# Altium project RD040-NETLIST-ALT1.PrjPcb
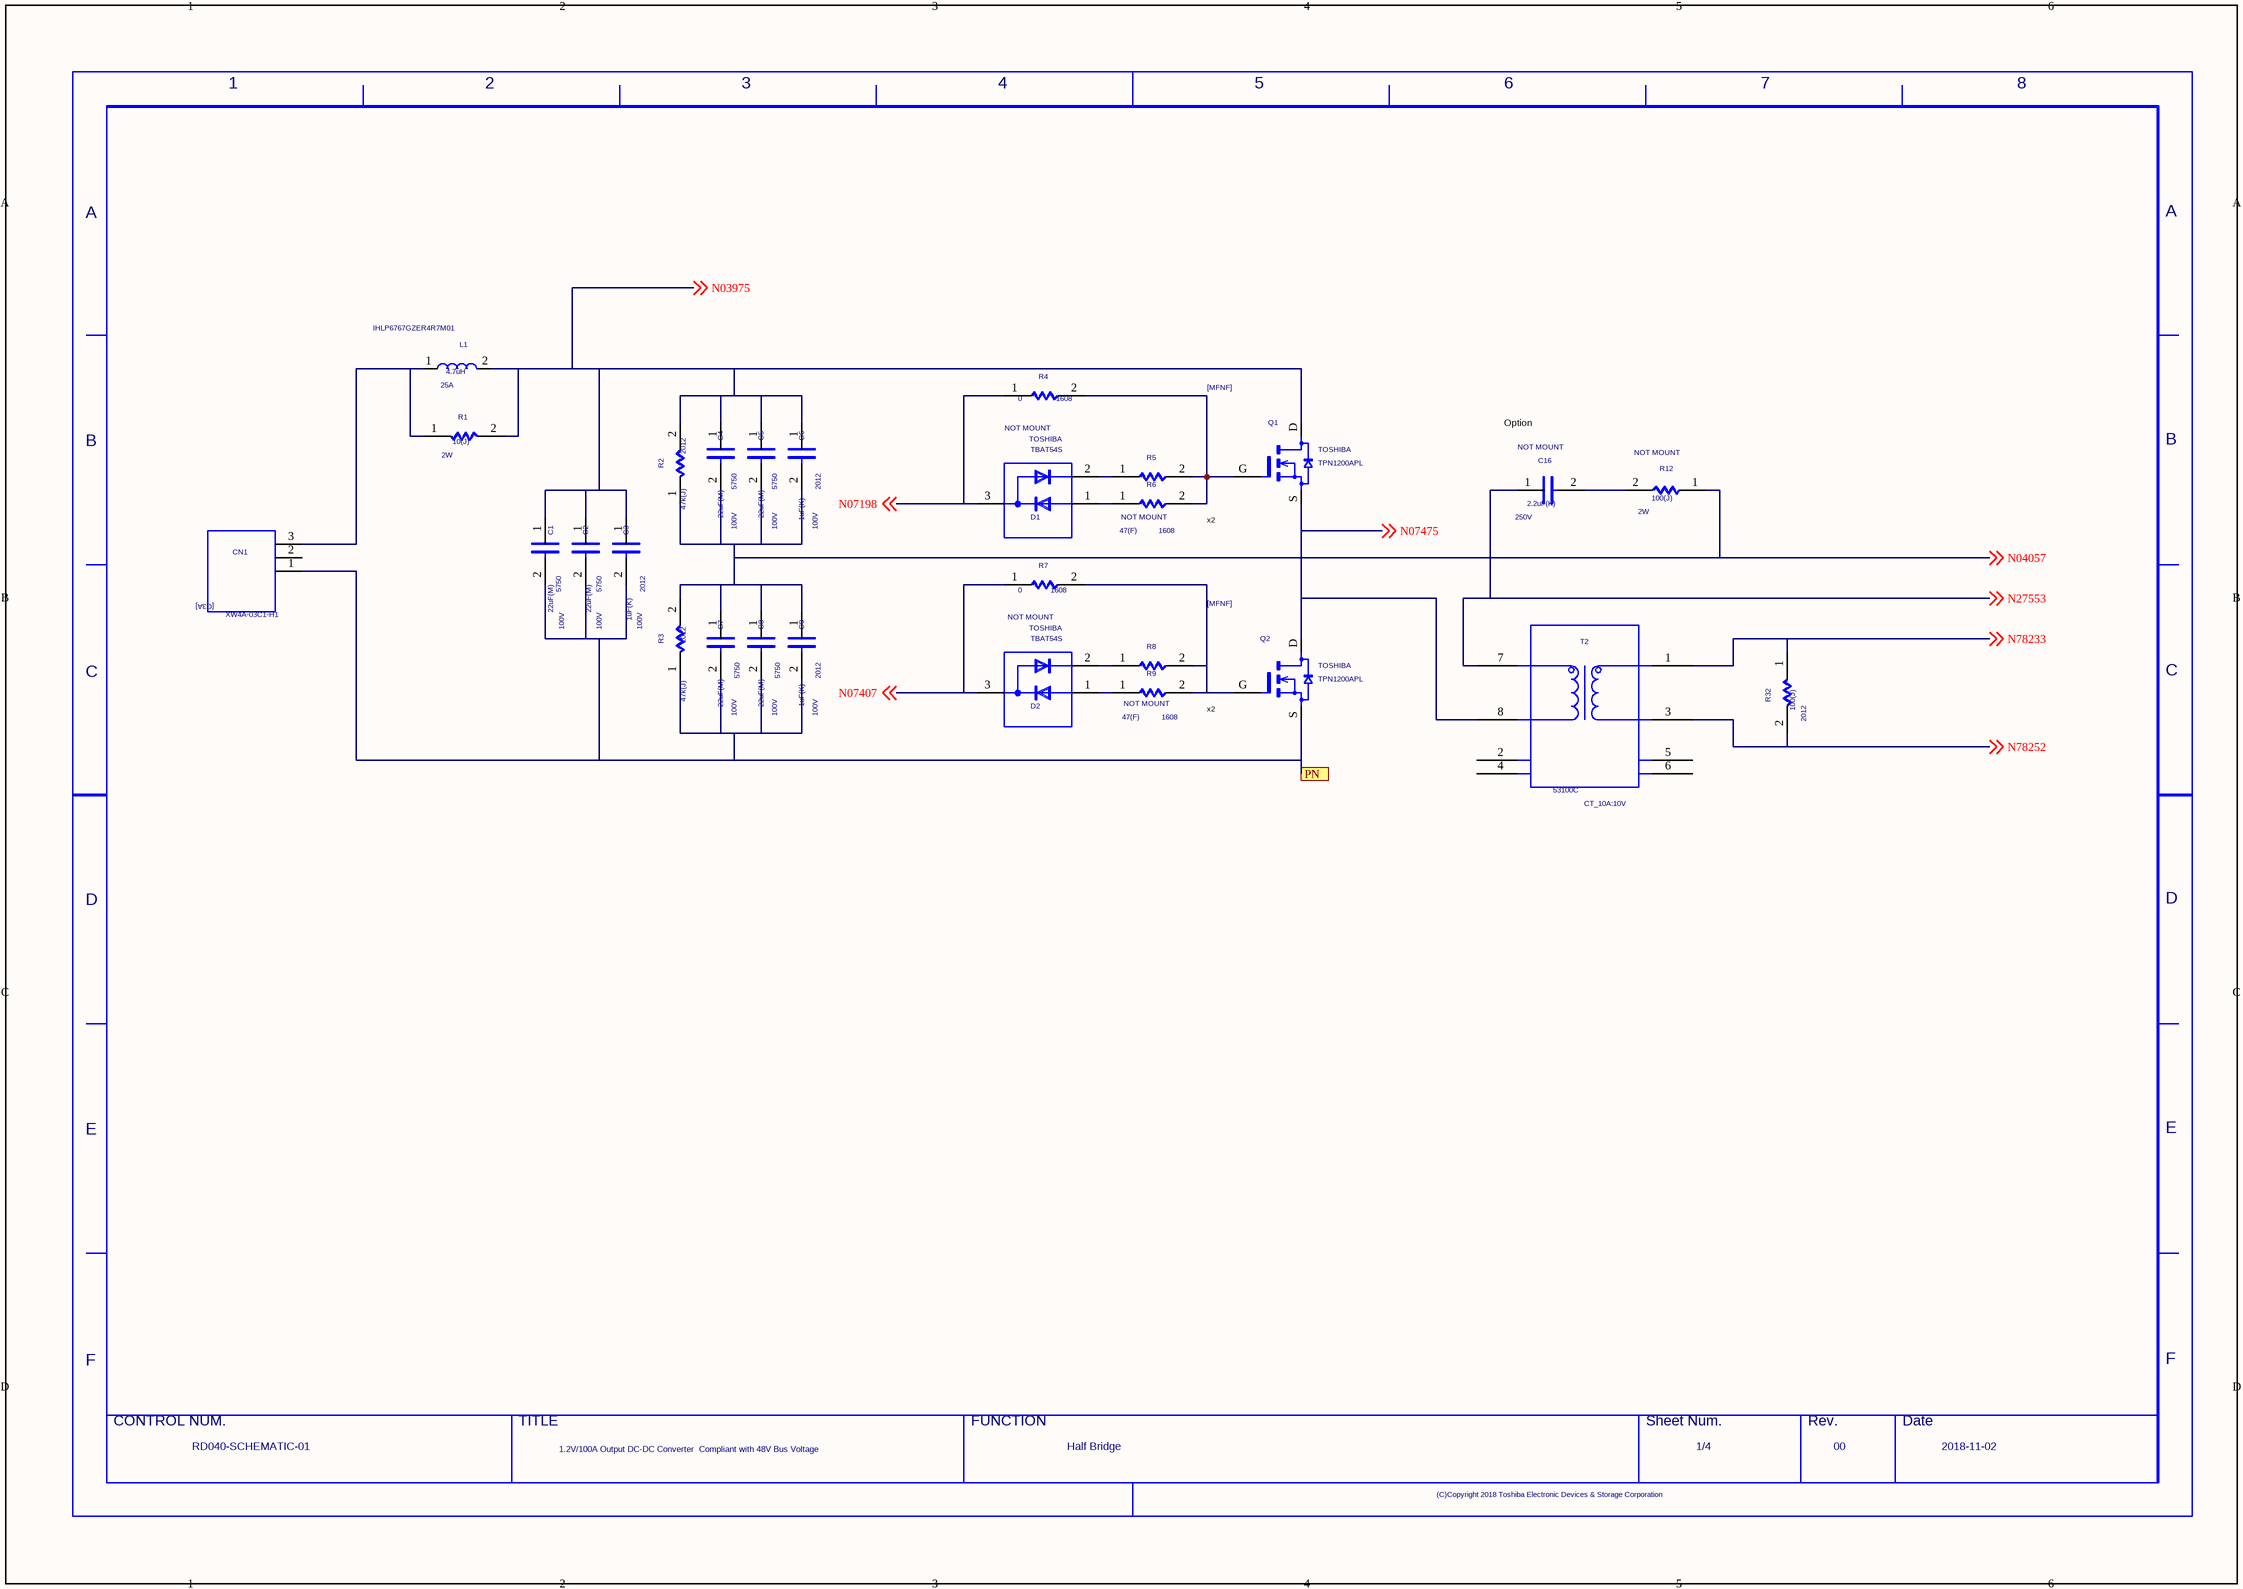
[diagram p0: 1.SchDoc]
4 sheets, 137 parts. Net scope: flat (ports and power ports of the same name join across sheets).
Sheets:
  1.SchDoc
  2.SchDoc
  3.SchDoc
  4.SchDoc

## Sheet 1.SchDoc
size 420 x 297 mm

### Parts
(Parts that share a designator on the sheet are numbered #1, #2 ... from top to bottom, then left to right.)
C1  COMPCOMMENT: 5750  VAL2: 100V  VAL1: 22uF(M)  [CHIP-5750]  (hidden comment: 22uF-M_100V)
C2  COMPCOMMENT: 5750  VAL2: 100V  VAL1: 22uF(M)  [CHIP-5750]  (hidden comment: 22uF-M_100V)
C3  VAL2: 100V  VAL1: 1uF(K)  COMPCOMMENT: 2012  [CHIP-2012]  (hidden comment: 1uF-K_100V)
C4  COMPCOMMENT: 5750  VAL2: 100V  VAL1: 22uF(M)  [CHIP-5750]  (hidden comment: 22uF-M_100V)
C5  COMPCOMMENT: 5750  VAL2: 100V  VAL1: 22uF(M)  [CHIP-5750]  (hidden comment: 22uF-M_100V)
C6  VAL2: 100V  VAL1: 1uF(K)  COMPCOMMENT: 2012  [CHIP-2012]  (hidden comment: 1uF-K_100V)
C7  COMPCOMMENT: 5750  VAL2: 100V  VAL1: 22uF(M)  [CHIP-5750]  (hidden comment: 22uF-M_100V)
C8  COMPCOMMENT: 5750  VAL2: 100V  VAL1: 22uF(M)  [CHIP-5750]  (hidden comment: 22uF-M_100V)
C9  COMPCOMMENT: 2012  VAL2: 100V  VAL1: 1uF(K)  [CHIP-2012]  (hidden comment: 1uF-K_100V)
C16  VAL1: 2.2uF(K)  VAL2: 250V  NOTMOUNT: NOT MOUNT  (hidden comment: C)
CN1  XW4A-03C1-H1  [SIP-3]
D1  NOTMOUNT: NOT MOUNT  USERCOMPTEXT3: TOSHIBA  [SOT23-3]  (hidden comment: TBAT54S)
D2  NOTMOUNT: NOT MOUNT  USERCOMPTEXT3: TOSHIBA  [SOT23-3]  (hidden comment: TBAT54S)
L1  VAL3: IHLP6767GZER4R7M01  VAL2: 25A  VAL1: 4.7uH  [SMD-6767]  (hidden comment: 4u7H-M_6767)
Q1  USERCOMPTEXT3: TOSHIBA  [TSON-8]  (hidden comment: TPN1200APL)
Q2  USERCOMPTEXT3: TOSHIBA  [TSON-8]  (hidden comment: TPN1200APL)
R1  VAL2: 2W  VAL1: 10(J)  [Axial-2]  (hidden comment: 10-J_2W)
R2  COMPCOMMENT: 2012  VAL1: 47k(J)  [CHIP-2012]  (hidden comment: 47k-J_2012)
R3  COMPCOMMENT: 2012  VAL1: 47k(J)  [CHIP-2012]  (hidden comment: 47k-J_2012)
R4  VAL1: 0  COMPCOMMENT: 1608  [CHIP-1608]  (hidden comment: NM_1608)
R5  NOTMOUNT: NOT MOUNT  VAL1: 47(F)  COMPCOMMENT: 1608  [CHIP-1608]  (hidden comment: 47-F_1608)
R6  47-F_1608  [CHIP-1608]  (value not drawn)
R7  VAL1: 0  COMPCOMMENT: 1608  [CHIP-1608]  (hidden comment: NM_1608)
R8  NOTMOUNT: NOT MOUNT  VAL1: 47(F)  COMPCOMMENT: 1608  [CHIP-1608]  (hidden comment: 47-F_1608)
R9  47-F_1608  [CHIP-1608]  (value not drawn)
R12  VAL2: 2W  VAL1: 100(J)  NOTMOUNT: NOT MOUNT  (hidden comment: R)
R32  COMPCOMMENT: 2012  VAL1: 100(J)  [CHIP-2012]  (hidden comment: 100-J_2012)
T2  CT_10A:10V
U?#1  DATE: 2018-11-02  FUNCTION: Half Bridge  TITLE: 1.2V/100A Output DC-DC Converter / Compliant with 48V Bus Voltage  DRAWINGNUMBER: RD040-SCHEMATIC-01  REVISION: 00  SHEETNUMBER: 1/4  (hidden comment: WAKU_DEF100_2018)

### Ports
PN

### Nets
N03975: C1.1 C2.1 C3.1 C4.1 C5.1 C6.1 L1.2 Q1.D R1.2 R2.2 ; off-sheet N03975
N04057: C4.2 C5.2 C6.2 C7.1 C8.1 C9.1 R2.1 R3.2 R12.1 ; off-sheet N04057
N07028: Q1.G R4.2 R5.2 R6.2
N07195: Q2.G R7.2 R8.2 R9.2
N07198: D1.3 R4.1 ; off-sheet N07198
N07407: D2.3 R7.1 ; off-sheet N07407
N07475: Q1.S Q2.D T2.8 ; off-sheet N07475
N08432: CN1.3 L1.1 R1.1
N27526: C16.2 R12.2
N27553: C16.1 T2.7 ; off-sheet N27553
N75033: D1.1 R6.1
N75062: D1.2 R5.1
N76065: D2.1 R9.1
N76205: D2.2 R8.1
N78233: R32.1 T2.1 ; off-sheet N78233
N78252: R32.2 T2.3 ; off-sheet N78252
SIG170: C1.2 C2.2 C3.2 C7.2 C8.2 C9.2 CN1.1 Q2.S R3.1 ; port PN

Not connected (* = marked no-connect by the designer): CN1 2; T2 2 4 5 6

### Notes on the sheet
- Option
- x2

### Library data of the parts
C1 = C: OriginalSymbolOrigin: (2540,7620); VAL3: KRM55WR72A226M; COMPONENTNAME: C_C; MAKER: Murata; INSTANCENAME: I04446; SAVECOUNT: 1; UPDATETIME: 16:59:57; UPDATEUSER: w20070dm; PIN NAMES VISIBLE: False; PIN NAMES ROTATE: True
C2 = C: OriginalSymbolOrigin: (2540,7620); VAL3: KRM55WR72A226M; COMPONENTNAME: C_C; MAKER: Murata; INSTANCENAME: I04482; SAVECOUNT: 1; UPDATETIME: 16:59:57; UPDATEUSER: w20070dm; PIN NAMES VISIBLE: False; PIN NAMES ROTATE: True
C3 = C: OriginalSymbolOrigin: (2540,7620); VAL3: GRM21BC72A105K; COMPONENTNAME: C_C; MAKER: Murata; INSTANCENAME: I04414; SAVECOUNT: 1; UPDATETIME: 16:59:57; UPDATEUSER: w20070dm; PIN NAMES VISIBLE: False; PIN NAMES ROTATE: True
C4 = C: OriginalSymbolOrigin: (2540,7620); VAL3: KRM55WR72A226M; COMPONENTNAME: C_C; MAKER: Murata; INSTANCENAME: I60867; SAVECOUNT: 1; UPDATETIME: 16:59:57; UPDATEUSER: w20070dm; PIN NAMES VISIBLE: False; PIN NAMES ROTATE: True
C5 = C: OriginalSymbolOrigin: (2540,7620); VAL3: KRM55WR72A226M; COMPONENTNAME: C_C; MAKER: Murata; INSTANCENAME: I60839; SAVECOUNT: 1; UPDATETIME: 16:59:57; UPDATEUSER: w20070dm; PIN NAMES VISIBLE: False; PIN NAMES ROTATE: True
C6 = C: OriginalSymbolOrigin: (2540,7620); VAL3: GRM21BC72A105K; COMPONENTNAME: C_C; MAKER: Murata; INSTANCENAME: I60803; SAVECOUNT: 1; UPDATETIME: 16:59:57; UPDATEUSER: w20070dm; PIN NAMES VISIBLE: False; PIN NAMES ROTATE: True
C7 = C: OriginalSymbolOrigin: (2540,7620); VAL3: KRM55WR72A226M; COMPONENTNAME: C_C; MAKER: Murata; INSTANCENAME: I61562; SAVECOUNT: 1; UPDATETIME: 16:59:57; UPDATEUSER: w20070dm; PIN NAMES VISIBLE: False; PIN NAMES ROTATE: True
C8 = C: OriginalSymbolOrigin: (2540,7620); VAL3: KRM55WR72A226M; COMPONENTNAME: C_C; MAKER: Murata; INSTANCENAME: I61642; SAVECOUNT: 1; UPDATETIME: 16:59:57; UPDATEUSER: w20070dm; PIN NAMES VISIBLE: False; PIN NAMES ROTATE: True
C9 = C: OriginalSymbolOrigin: (2540,7620); VAL3: GRM21BC72A105K; COMPONENTNAME: C_C; MAKER: Murata; INSTANCENAME: I61594; SAVECOUNT: 1; UPDATETIME: 16:59:57; UPDATEUSER: w20070dm; PIN NAMES VISIBLE: False; PIN NAMES ROTATE: True
C16 = C: OriginalSymbolOrigin: (2540,7620); VAL3: ECQE2225KB
CN1 = C3A: PARTNAME: PIN-HEADER_3x1; SAVEAREA0: -6798,-236,26764,20869; TIME: 09:53:04; UPDATEUSER: tomizawa-y; UPDATETIME: 09:53:12; SAVECOUNT: 2; OriginalSymbolOrigin: (2540,17780); FUNCTION: PIN-HEADER_3x1_PIN-HEADER_3x1.Normal_package; MAKER: Omron; INSTANCENAME: I08244; NUMBER DEVICES IN PACKAGE: 1; PIN NAMES VISIBLE: False; PIN NAMES ROTATE: True
D1 = DML: PARTNAME: 1SS226; SAVEAREA0: -6496,-188,29064,18281; TIME: 11:11:28; UPDATEUSER: cae; UPDATETIME: 11:19:31; SAVECOUNT: 3; OriginalSymbolOrigin: (5080,17780); FUNCTION: 1SS226_1SS226.Normal_package; INSTANCENAME: I71543; NUMBER DEVICES IN PACKAGE: 1; PIN NAMES VISIBLE: False; PIN NAMES ROTATE: True
D2 = DML: PARTNAME: 1SS226; SAVEAREA0: -6496,-188,29064,18281; TIME: 11:11:28; UPDATEUSER: cae; UPDATETIME: 11:19:31; SAVECOUNT: 3; OriginalSymbolOrigin: (5080,17780); FUNCTION: 1SS226_1SS226.Normal_package; INSTANCENAME: I78427; NUMBER DEVICES IN PACKAGE: 1; PIN NAMES VISIBLE: False; PIN NAMES ROTATE: True
L1 = L: PARTNAME: INDUCTOR; OriginalSymbolOrigin: (2540,5080); COMPONENTNAME: INDUCTOR_INDUCTOR; MAKER: Vishay; INSTANCENAME: I20636496; SAVECOUNT: 1; UPDATETIME: 16:59:57; UPDATEUSER: w20070dm; PIN NAMES VISIBLE: False; ORDER: 0; PIN NAMES ROTATE: True
Q1 = MFNF: PARTNAME: MOSFET_N(D); SAVECOUNT: 11; SAVEAREA0: -7027,-292,21786,15988; OriginalSymbolOrigin: (5080,12700); FUNCTION: MOSFET_N(D)_MOSFET_N(D).Normal_package; INSTANCENAME: I69029; UPDATETIME: 16:59:57; UPDATEUSER: w20070dm; NUMBER DEVICES IN PACKAGE: 1; PIN NAMES VISIBLE: False; PIN NAMES ROTATE: True
Q2 = MFNF: PARTNAME: MOSFET_N(D); SAVECOUNT: 11; SAVEAREA0: -7027,-292,21786,15988; OriginalSymbolOrigin: (5080,12700); FUNCTION: MOSFET_N(D)_MOSFET_N(D).Normal_package; INSTANCENAME: I69405; UPDATETIME: 16:59:57; UPDATEUSER: w20070dm; NUMBER DEVICES IN PACKAGE: 1; PIN NAMES VISIBLE: False; PIN NAMES ROTATE: True
R1 = R: OriginalSymbolOrigin: (5080,5080); VAL3: MOS2CT52A100J; COMPONENTNAME: R_R; MAKER: ROHM; INSTANCENAME: I62527; SAVECOUNT: 1; UPDATETIME: 16:59:57; UPDATEUSER: w20070dm; PIN NAMES VISIBLE: False; PIN NAMES ROTATE: True
R2 = R: OriginalSymbolOrigin: (5080,5080); VAL2: 0.4W; VAL3: ESR10EZPJ473; COMPONENTNAME: R_R; MAKER: ROHM; INSTANCENAME: I20654113; SAVECOUNT: 1; UPDATETIME: 16:59:57; UPDATEUSER: w20070dm; PIN NAMES VISIBLE: False; PIN NAMES ROTATE: True
R3 = R: OriginalSymbolOrigin: (5080,5080); VAL2: 0.4W; VAL3: ESR10EZPJ473; COMPONENTNAME: R_R; MAKER: ROHM; INSTANCENAME: I61482; SAVECOUNT: 1; UPDATETIME: 16:59:57; UPDATEUSER: w20070dm; PIN NAMES VISIBLE: False; PIN NAMES ROTATE: True
R4 = R: OriginalSymbolOrigin: (5080,5080); VAL3: MCR03EZHJ000; VAL2: 1/8W; COMPONENTNAME: R_R; MAKER: KOA; INSTANCENAME: I75159; SAVECOUNT: 1; UPDATETIME: 16:59:57; UPDATEUSER: w20070dm; PIN NAMES VISIBLE: False; PIN NAMES ROTATE: True
R5 = R: OriginalSymbolOrigin: (5080,5080); VAL3: RK73H1JTTD47R0F; COMPONENTNAME: R_R; MAKER: KOA; INSTANCENAME: I74967; SAVECOUNT: 1; UPDATETIME: 16:59:57; UPDATEUSER: w20070dm; PIN NAMES VISIBLE: False; PIN NAMES ROTATE: True
R6 = R: OriginalSymbolOrigin: (5080,5080); NOTMOUNT: NOT MOUNT; VAL1: 47(F); COMPCOMMENT: 1608; VAL3: RK73H1JTTD47R0F; COMPONENTNAME: R_R; MAKER: KOA; INSTANCENAME: I74991; SAVECOUNT: 1; UPDATETIME: 16:59:57; UPDATEUSER: w20070dm; PIN NAMES VISIBLE: False; PIN NAMES ROTATE: True
R7 = R: OriginalSymbolOrigin: (5080,5080); VAL2: 1/8W; VAL3: MCR03EZHJ000; COMPONENTNAME: R_R; MAKER: KOA; INSTANCENAME: I76137; SAVECOUNT: 1; UPDATETIME: 16:59:57; UPDATEUSER: w20070dm; PIN NAMES VISIBLE: False; PIN NAMES ROTATE: True
R8 = R: OriginalSymbolOrigin: (5080,5080); VAL3: RK73H1JTTD47R0F; COMPONENTNAME: R_R; MAKER: KOA; INSTANCENAME: I76161; SAVECOUNT: 1; UPDATETIME: 16:59:57; UPDATEUSER: w20070dm; PIN NAMES VISIBLE: False; PIN NAMES ROTATE: True
R9 = R: OriginalSymbolOrigin: (5080,5080); NOTMOUNT: NOT MOUNT; VAL1: 47(F); COMPCOMMENT: 1608; VAL3: RK73H1JTTD47R0F; COMPONENTNAME: R_R; MAKER: KOA; INSTANCENAME: I76085; SAVECOUNT: 1; UPDATETIME: 16:59:57; UPDATEUSER: w20070dm; PIN NAMES VISIBLE: False; PIN NAMES ROTATE: True
R12 = R: OriginalSymbolOrigin: (5080,5080); VAL3: MOS2CT52A101J
R32 = R: OriginalSymbolOrigin: (5080,5080); VAL3: ESR10EZPJ101; COMPONENTNAME: R_R; MAKER: ROHM; INSTANCENAME: I78881; SAVECOUNT: 1; UPDATETIME: 16:59:57; UPDATEUSER: w20070dm; PIN NAMES VISIBLE: False; PIN NAMES ROTATE: True
T2 = 53100C: PARTNAME: AF-TRANS(2B_murata); SAVEAREA0: -14581,-371,55282,35914; SAVECOUNT: 9; TIME: 14:27:07; UPDATEUSER: cae; UPDATETIME: 15:56:07; OriginalSymbolOrigin: (7620,33020); FUNCTION: AF-TRANS(2B_murata)_AF-TRANS(2B_murata).Normal_package; MAKER: Murata; INSTANCENAME: I67135; NUMBER DEVICES IN PACKAGE: 1; PIN NAMES VISIBLE: False; ORDER: 0; PIN NUMBERS VISIBLE: True
U?#1 = WAKU_DEF100_2018: PLOTTIME: HH:MM; SAVEAREA0: -45080,-4508,463680,304612; TIME: 14:09:12; UPDATEUSER: cae; UPDATETIME: 09:58:42; SAVECOUNT: 4; OriginalSymbolOrigin: (10160,284480)

## Sheet 2.SchDoc
size 420 x 297 mm
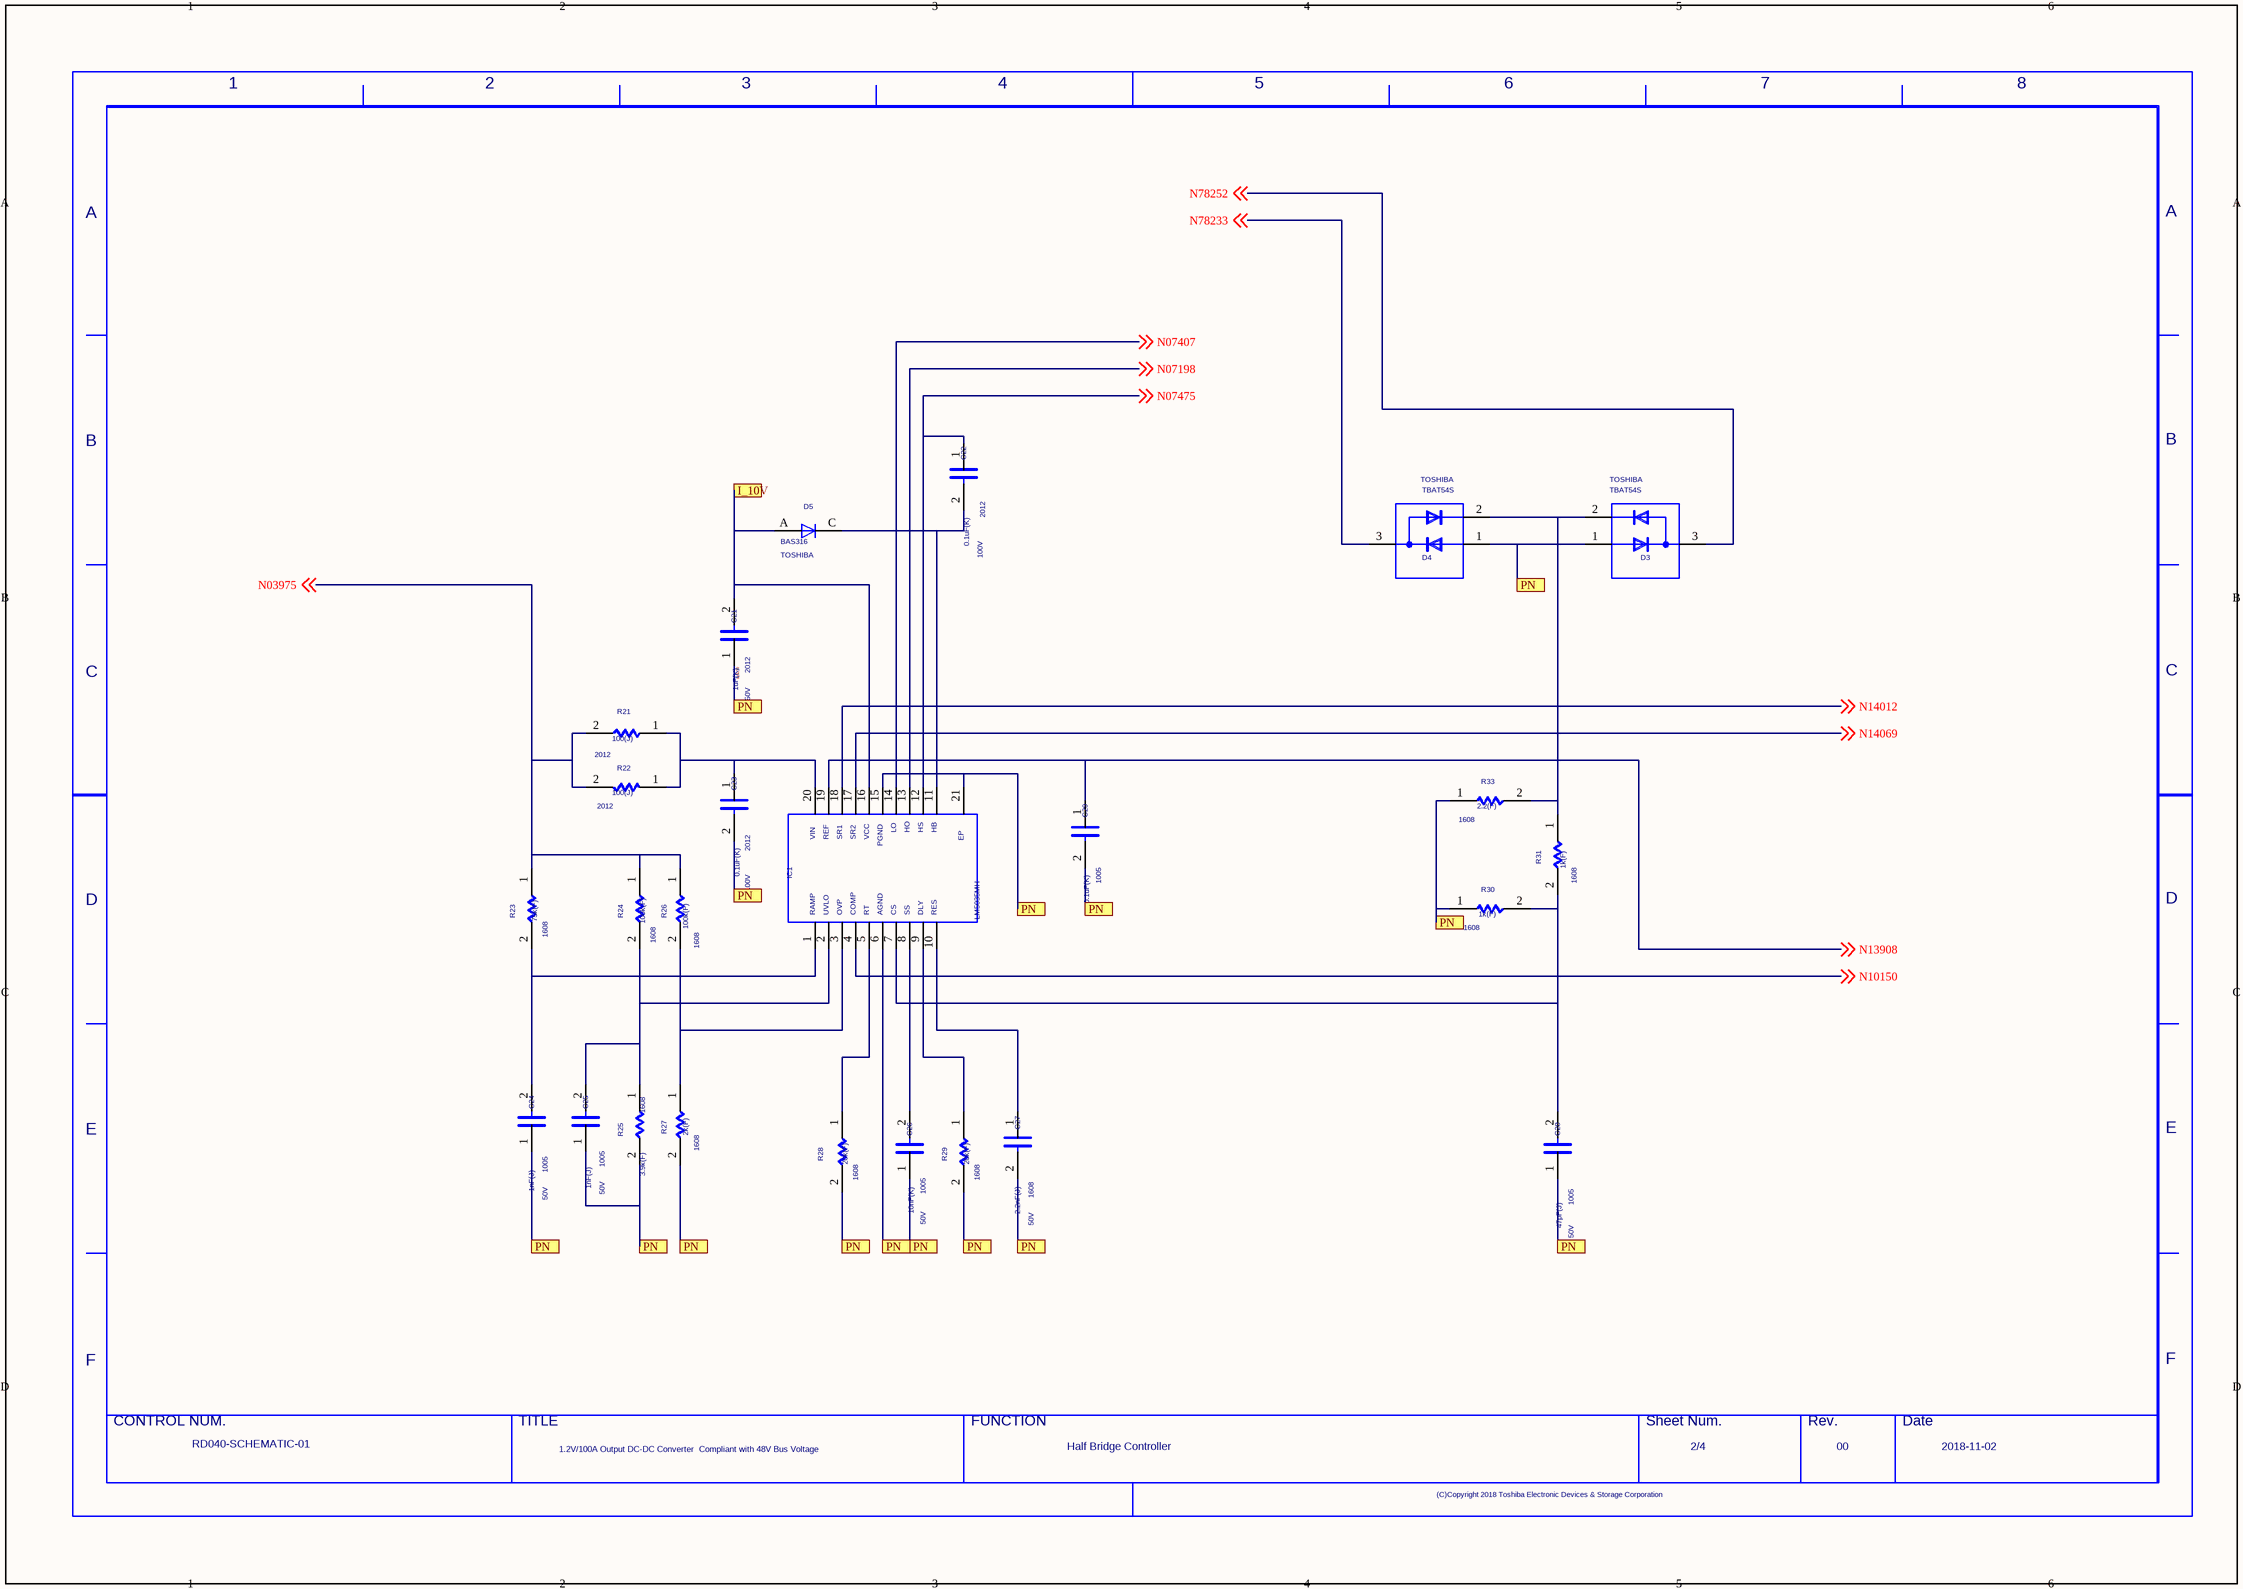
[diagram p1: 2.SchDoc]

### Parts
(Parts that share a designator on the sheet are numbered #1, #2 ... from top to bottom, then left to right.)
C21  VAL2: 50V  VAL1: 1uF(K)  COMPCOMMENT: 2012  [CHIP-2012]  (hidden comment: 1uF-K_2012)
C22  VAL2: 100V  VAL1: 0.1uF(K)  COMPCOMMENT: 2012  [CHIP-2012]  (hidden comment: 0u1F-K_100V)
C23  VAL2: 100V  VAL1: 0.1uF(K)  COMPCOMMENT: 2012  [CHIP-2012]  (hidden comment: 0u1F-K_100V)
C24  VAL2: 50V  COMPCOMMENT: 1005  VAL1: 1nF(J)  [CHIP-1005]  (hidden comment: 1000pF-J_1005)
C25  VAL2: 50V  VAL1: 1nF(J)  COMPCOMMENT: 1005  [CHIP-1005]  (hidden comment: 1000pF-J_1005)
C26  VAL2: 50V  VAL1: 10nF(K)  COMPCOMMENT: 1005  [CHIP-1005]  (hidden comment: 10nF-J_1005)
C27  VAL2: 50V  VAL1: 2.2nF(J)  COMPCOMMENT: 1608  [CHIP-1608]  (hidden comment: 2200pF-J_1608)
C28  VAL2: 50V  VAL1: 47pF(J)  COMPCOMMENT: 1005  [CHIP-1005]  (hidden comment: 47pF-J_1005)
C29  VAL2: 50V  VAL1: 0.1uF(K)  COMPCOMMENT: 1005  [CHIP-1005]  (hidden comment: 0u1F-K_1005)
D3  USERCOMPTEXT3: TOSHIBA  [SOT23-3]  (hidden comment: TBAT54S)
D4  USERCOMPTEXT3: TOSHIBA  [SOT23-3]  (hidden comment: TBAT54S)
D5  USERCOMPTEXT3: TOSHIBA  [CHIP-2012]  (hidden comment: BAS316)
IC1  LM5035MH
R21  VAL1: 100(J)  COMPCOMMENT: 2012  [CHIP-2012]  (hidden comment: 100-J_2012)
R22  VAL1: 100(J)  COMPCOMMENT: 2012  [CHIP-2012]  (hidden comment: 100-J_2012)
R23  COMPCOMMENT: 1608  VAL1: 75k(F)  [CHIP-1608]  (hidden comment: 75k-F_1608)
R24  COMPCOMMENT: 1608  VAL1: 100k(F)  [CHIP-1608]  (hidden comment: 100k-F_1608)
R25  VAL1: 3.9k(F)  COMPCOMMENT: 1608  [CHIP-1608]  (hidden comment: 10k-F_1608)
R26  VAL1: 100k(F)  COMPCOMMENT: 1608  [CHIP-1608]  (hidden comment: 100k-F_1608)
R27  VAL1: 2k(F)  COMPCOMMENT: 1608  [CHIP-1608]  (hidden comment: 2k0-F_1608)
R28  VAL1: 20k(F)  COMPCOMMENT: 1608  [CHIP-1608]  (hidden comment: 20k-F_1608)
R29  VAL1: 20k(F)  COMPCOMMENT: 1608  [CHIP-1608]  (hidden comment: 20k-F_1608)
R30  VAL1: 1k(F)  COMPCOMMENT: 1608  [CHIP-1608]  (hidden comment: NM_1608)
R31  VAL1: 1k(F)  COMPCOMMENT: 1608  [CHIP-1608]  (hidden comment: 1k0-F_1608)
R33  VAL1: 2.2(F)  COMPCOMMENT: 1608  [CHIP-1608]  (hidden comment: 22-F_1608)
U?#2  DATE: 2018-11-02  FUNCTION: Half Bridge Controller  DRAWINGNUMBER: RD040-SCHEMATIC-01  SHEETNUMBER: 2/4  REVISION: 00  TITLE: 1.2V/100A Output DC-DC Converter / Compliant with 48V Bus Voltage  (hidden comment: WAKU_DEF100_2018)

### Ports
I_10V, PN

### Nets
N03975: R21.2 R22.2 R23.1 R24.1 R26.1 ; off-sheet N03975
N07198: IC1.13 ; off-sheet N07198
N07407: IC1.14 ; off-sheet N07407
N07475: C22.1 IC1.12 ; off-sheet N07475
N09234: C24.2 IC1.1 R23.2
N09291: C25.2 IC1.2 R24.2 R25.1
N09925: IC1.3 R26.2 R27.1
N10150: IC1.4 ; off-sheet N10150
N10207: IC1.5 R28.1
N10599: C26.2 IC1.8
N10798: IC1.9 R29.1
N10927: C27.1 IC1.10
N11642: C28.2 IC1.7 R30.2 R31.2
N12755: C22.2 D5.C IC1.11
N12929: C23.1 IC1.20 R21.1 R22.1
N13908: C29.1 IC1.19 ; off-sheet N13908
N14012: IC1.18 ; off-sheet N14012
N14069: IC1.17 ; off-sheet N14069
N78233: D4.3 ; off-sheet N78233
N78252: D3.3 ; off-sheet N78252
N78738: D3.2 D4.2 R31.1 R33.2
SIG170: C21.1 C23.2 C24.1 C25.1 C26.1 C27.2 C28.1 C29.2 D3.1 D4.1 IC1.6 IC1.15 IC1.21 R25.2 R27.2 R28.2 R29.2 R30.1 R33.1 ; port PN
NetC13_1: C21.2 D5.A IC1.16 ; port I_10V

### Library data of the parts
C21 = C: OriginalSymbolOrigin: (2540,7620); VAL3: GCM21BR71H105K; COMPONENTNAME: C_C; MAKER: Murata; INSTANCENAME: I16847; SAVECOUNT: 1; UPDATETIME: 16:59:57; UPDATEUSER: w20070dm; PIN NAMES VISIBLE: False; PIN NAMES ROTATE: True
C22 = C: OriginalSymbolOrigin: (2540,7620); VAL3: GRM21BR72A104K; COMPONENTNAME: C_C; MAKER: Murata; INSTANCENAME: I12586; SAVECOUNT: 1; UPDATETIME: 16:59:57; UPDATEUSER: w20070dm; PIN NAMES VISIBLE: False; PIN NAMES ROTATE: True
C23 = C: OriginalSymbolOrigin: (2540,7620); VAL3: GRM21BR72A104K; COMPONENTNAME: C_C; MAKER: Murata; INSTANCENAME: I13088; SAVECOUNT: 1; UPDATETIME: 16:59:57; UPDATEUSER: w20070dm; PIN NAMES VISIBLE: False; PIN NAMES ROTATE: True
C24 = C: OriginalSymbolOrigin: (2540,7620); VAL3: GRM1552C1H102J; COMPONENTNAME: C_C; MAKER: MURATA; INSTANCENAME: I20645479; SAVECOUNT: 1; UPDATETIME: 16:59:57; UPDATEUSER: w20070dm; PIN NAMES VISIBLE: False; PIN NAMES ROTATE: True
C25 = C: OriginalSymbolOrigin: (2540,7620); VAL3: GRM1552C1H102J; COMPONENTNAME: C_C; MAKER: MURATA; INSTANCENAME: I09708; SAVECOUNT: 1; UPDATETIME: 16:59:57; UPDATEUSER: w20070dm; PIN NAMES VISIBLE: False; PIN NAMES ROTATE: True
C26 = C: OriginalSymbolOrigin: (2540,7620); VAL3: GCM155R11H103K; COMPONENTNAME: C_C; MAKER: MURATA; INSTANCENAME: I10622; SAVECOUNT: 1; UPDATETIME: 16:59:57; UPDATEUSER: w20070dm; PIN NAMES VISIBLE: False; PIN NAMES ROTATE: True
C27 = C: OriginalSymbolOrigin: (2540,7620); VAL3: GRM1882C1H222J; COMPONENTNAME: C_C; MAKER: MURATA; INSTANCENAME: I79432; SAVECOUNT: 1; UPDATETIME: 16:59:57; UPDATEUSER: w20070dm; PIN NAMES VISIBLE: False; PIN NAMES ROTATE: True
C28 = C: OriginalSymbolOrigin: (2540,7620); VAL3: GRM1552C1H470J; COMPONENTNAME: C_C; MAKER: MURATA; INSTANCENAME: I10408; SAVECOUNT: 1; UPDATETIME: 16:59:57; UPDATEUSER: w20070dm; PIN NAMES VISIBLE: False; PIN NAMES ROTATE: True
C29 = C: OriginalSymbolOrigin: (2540,7620); VAL3: GCM155R71H104K; COMPONENTNAME: C_C; MAKER: Murata; INSTANCENAME: I82167; SAVECOUNT: 1; UPDATETIME: 16:59:57; UPDATEUSER: w20070dm; PIN NAMES VISIBLE: False; PIN NAMES ROTATE: True
D3 D4 = DML: PARTNAME: 1SS226; SAVEAREA0: -6496,-188,29064,18281; TIME: 11:11:28; UPDATEUSER: cae; UPDATETIME: 11:19:31; SAVECOUNT: 3; OriginalSymbolOrigin: (5080,17780); FUNCTION: 1SS226_1SS226.Normal_package; INSTANCENAME: I78476; NUMBER DEVICES IN PACKAGE: 1; PIN NAMES VISIBLE: False; PIN NAMES ROTATE: True
D5 = D: PARTNAME: DIODE; SAVEAREA0: -225,-91,12804,7836; SAVECOUNT: 3; TIME: 14:49:55; UPDATEUSER: 19870035; UPDATETIME: 14:20:16; OriginalSymbolOrigin: (5080,5080); COMPONENTNAME: DIODE_DIODE; INSTANCENAME: I31395; NUMBER DEVICES IN PACKAGE: 1; PIN NAMES VISIBLE: False; PIN NAMES ROTATE: True
IC1 = LM5035MH: TIME: 16:59:57; UPDATEUSER: cae; UPDATETIME: 13:47:07; SAVECOUNT: 6; SAVEAREA0: -25727,-431,55556,41786; OriginalSymbolOrigin: (5080,38100)
R21 = R: OriginalSymbolOrigin: (5080,5080); VAL2: 0.4W; VAL3: ESR10EZPJ101; COMPONENTNAME: R_R; MAKER: ROHM; INSTANCENAME: I13412; SAVECOUNT: 1; UPDATETIME: 16:59:57; UPDATEUSER: w20070dm; PIN NAMES VISIBLE: False; PIN NAMES ROTATE: True
R22 = R: OriginalSymbolOrigin: (5080,5080); VAL3: ESR10EZPJ101; COMPONENTNAME: R_R; MAKER: ROHM; INSTANCENAME: I13353; SAVECOUNT: 1; UPDATETIME: 16:59:57; UPDATEUSER: w20070dm; PIN NAMES VISIBLE: False; PIN NAMES ROTATE: True
R23 = R: OriginalSymbolOrigin: (5080,5080); VAL3: RK73H1JTTD7502F; COMPONENTNAME: R_R; MAKER: KOA; INSTANCENAME: I20641644; SAVECOUNT: 1; UPDATETIME: 16:59:57; UPDATEUSER: w20070dm; PIN NAMES VISIBLE: False; PIN NAMES ROTATE: True
R24 = R: OriginalSymbolOrigin: (5080,5080); VAL3: RK73H1JTTD1003F; COMPONENTNAME: R_R; MAKER: KOA; INSTANCENAME: I09414; SAVECOUNT: 1; UPDATETIME: 16:59:57; UPDATEUSER: w20070dm; PIN NAMES VISIBLE: False; PIN NAMES ROTATE: True
R25 = R: OriginalSymbolOrigin: (5080,5080); VAL2: 1/10W; VAL3: RK73H1JTTD3901F; COMPONENTNAME: R_R; MAKER: KOA; INSTANCENAME: I09474; SAVECOUNT: 1; UPDATETIME: 16:59:57; UPDATEUSER: w20070dm; PIN NAMES VISIBLE: False; PIN NAMES ROTATE: True
R26 = R: OriginalSymbolOrigin: (5080,5080); VAL3: RK73H1JTTD1003F; COMPONENTNAME: R_R; MAKER: KOA; INSTANCENAME: I09859; SAVECOUNT: 1; UPDATETIME: 16:59:57; UPDATEUSER: w20070dm; PIN NAMES VISIBLE: False; PIN NAMES ROTATE: True
R27 = R: OriginalSymbolOrigin: (5080,5080); VAL3: RK73H1JTTD2001F; VAL2: 1/10W; COMPONENTNAME: R_R; MAKER: KOA; INSTANCENAME: I09883; SAVECOUNT: 1; UPDATETIME: 16:59:57; UPDATEUSER: w20070dm; PIN NAMES VISIBLE: False; PIN NAMES ROTATE: True
R28 = R: OriginalSymbolOrigin: (5080,5080); VAL2: 1/10W; VAL3: RK73H1JTTD2002F; COMPONENTNAME: R_R; MAKER: KOA; INSTANCENAME: I10331; SAVECOUNT: 1; UPDATETIME: 16:59:57; UPDATEUSER: w20070dm; PIN NAMES VISIBLE: False; PIN NAMES ROTATE: True
R29 = R: OriginalSymbolOrigin: (5080,5080); VAL3: RK73H1JTTD2002F; VAL2: 1/10W; COMPONENTNAME: R_R; MAKER: KOA; INSTANCENAME: I10792; SAVECOUNT: 1; UPDATETIME: 16:59:57; UPDATEUSER: w20070dm; PIN NAMES VISIBLE: False; PIN NAMES ROTATE: True
R30 = R: OriginalSymbolOrigin: (5080,5080); VAL2: 1/10W; VAL3: RK73H1JTTD1001F; COMPONENTNAME: R_R; MAKER: KOA; INSTANCENAME: I79043; SAVECOUNT: 1; UPDATETIME: 16:59:57; UPDATEUSER: w20070dm; PIN NAMES VISIBLE: False; PIN NAMES ROTATE: True
R31 = R: OriginalSymbolOrigin: (5080,5080); VAL3: RK73H1JTTD1001F; VAL2: 1/10W; COMPONENTNAME: R_R; MAKER: KOA; INSTANCENAME: I12478; SAVECOUNT: 1; UPDATETIME: 16:59:57; UPDATEUSER: w20070dm; PIN NAMES VISIBLE: False; PIN NAMES ROTATE: True
R33 = R: OriginalSymbolOrigin: (5080,5080); VAL3: RK73H1JTTD22R0F; VAL2: 1/10W; COMPONENTNAME: R_R; MAKER: KOA; INSTANCENAME: I113731; SAVECOUNT: 1; UPDATETIME: 16:59:57; UPDATEUSER: w20070dm; PIN NAMES VISIBLE: False; PIN NAMES ROTATE: True
U?#2 = WAKU_DEF100_2018: PLOTTIME: HH:MM; SAVEAREA0: -45080,-4508,463680,304612; TIME: 13:53:51; UPDATEUSER: cae; UPDATETIME: 09:58:42; SAVECOUNT: 4; OriginalSymbolOrigin: (10160,284480)

## Sheet 3.SchDoc
size 420 x 297 mm
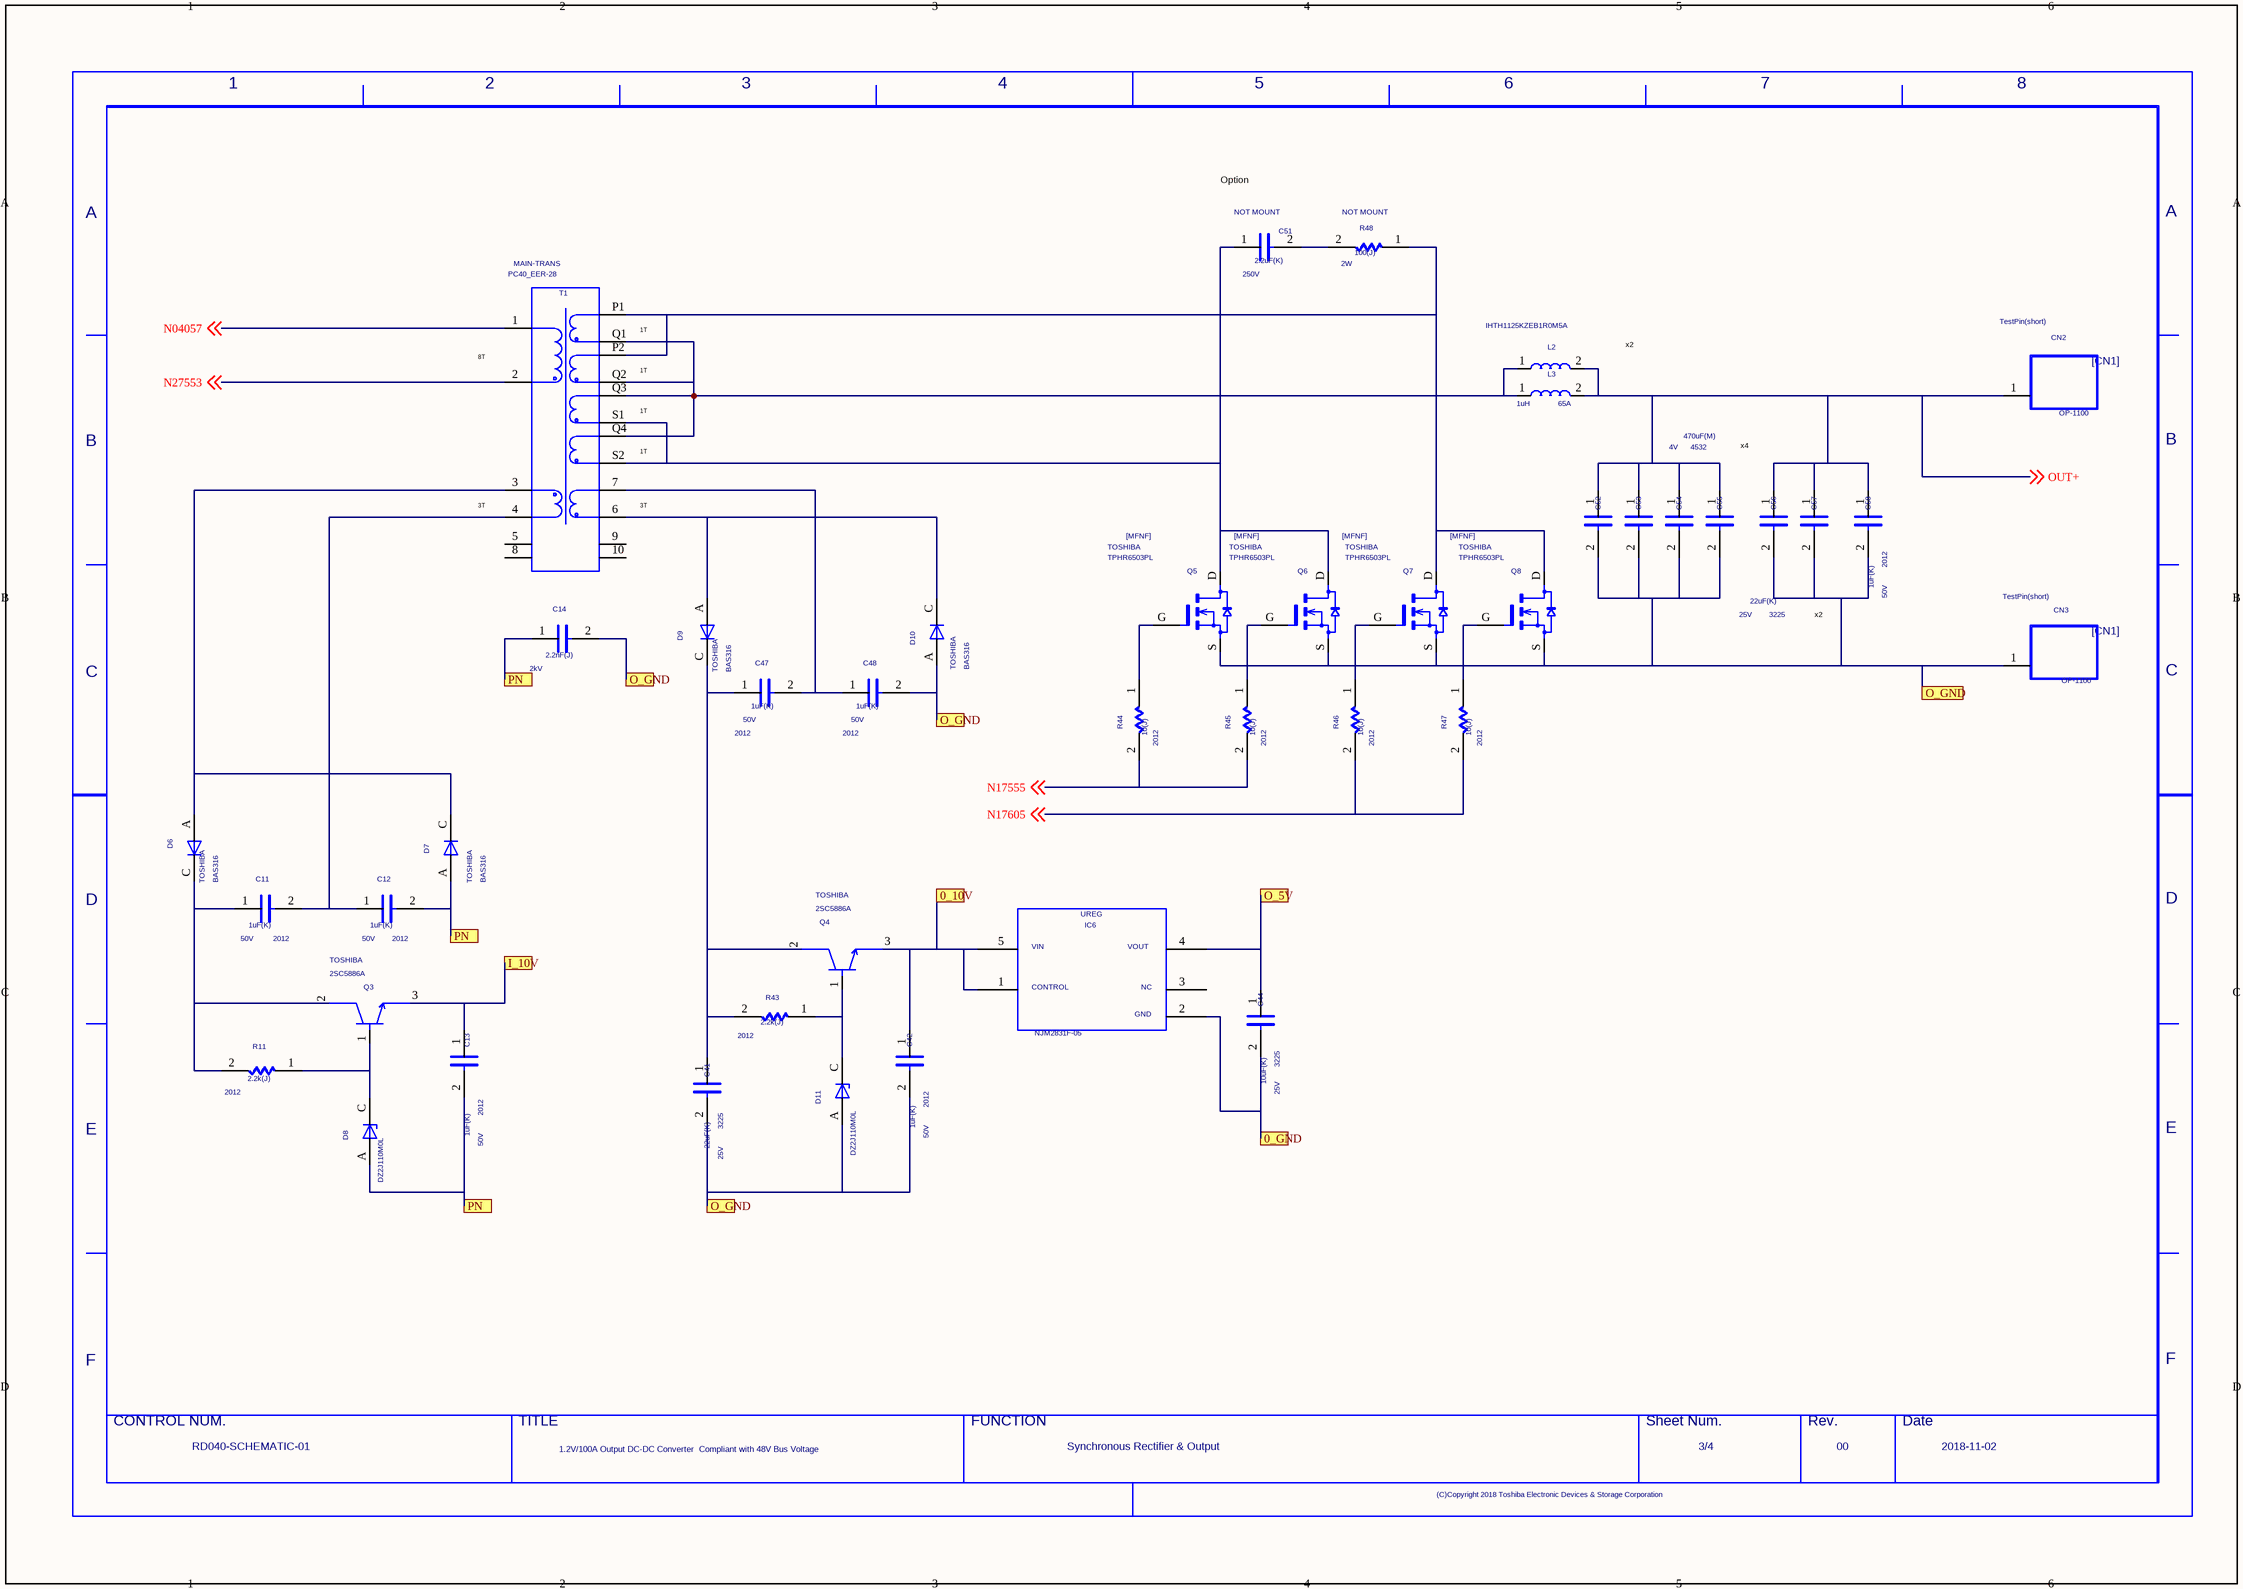
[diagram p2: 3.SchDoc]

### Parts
(Parts that share a designator on the sheet are numbered #1, #2 ... from top to bottom, then left to right.)
C11  VAL2: 50V  VAL1: 1uF(K)  COMPCOMMENT: 2012  [CHIP-2012]  (hidden comment: 1uF-K_2012)
C12  VAL2: 50V  VAL1: 1uF(K)  COMPCOMMENT: 2012  [CHIP-2012]  (hidden comment: 1uF-K_2012)
C13  COMPCOMMENT: 2012  VAL2: 50V  VAL1: 1uF(K)  [CHIP-2012]  (hidden comment: 1uF-K_2012)
C14  VAL2: 2kV  VAL1: 2.2nF(J)  [Radial-2]  (hidden comment: 2200pF-J_2kV)
C41  VAL2: 25V  COMPCOMMENT: 3225  VAL1: 22uF(K)  [CHIP-3225]  (hidden comment: 22uF-K_3225)
C42  VAL2: 50V  VAL1: 1uF(K)  COMPCOMMENT: 2012  [CHIP-2012]  (hidden comment: 1uF-K_2012)
C44  VAL2: 25V  COMPCOMMENT: 3225  VAL1: 10uF(K)  [CHIP-3225]  (hidden comment: 10uF-K_3225)
C47  VAL2: 50V  VAL1: 1uF(K)  COMPCOMMENT: 2012  [CHIP-2012]  (hidden comment: 1uF-K_2012)
C48  VAL2: 50V  VAL1: 1uF(K)  COMPCOMMENT: 2012  [CHIP-2012]  (hidden comment: 1uF-K_2012)
C51  NOTMOUNT: NOT MOUNT  VAL2: 250V  VAL1: 2.2uF(K)  [Radial-2]  (hidden comment: NM_250V)
C52  VAL2: 4V  COMPCOMMENT: 4532  VAL1: 470uF(M)  [CHIP-4532]  (hidden comment: 470uF-M_4532)
C53  470uF-M_4532  [CHIP-4532]  (value not drawn)
C54  470uF-M_4532  [CHIP-4532]  (value not drawn)
C55  470uF-M_4532  [CHIP-4532]  (value not drawn)
C56  VAL2: 25V  COMPCOMMENT: 3225  VAL1: 22uF(K)  [CHIP-3225]  (hidden comment: 22uF-K_3225)
C57  22uF-K_3225  [CHIP-3225]  (value not drawn)
C58  VAL2: 50V  VAL1: 1uF(K)  COMPCOMMENT: 2012  [CHIP-2012]  (hidden comment: 1uF-K_2012)
CN2  COMPCOMMENT: TestPin(short)  [TH-4]  (hidden comment: OP-1100)
CN3  COMPCOMMENT: TestPin(short)  [TH-4]  (hidden comment: OP-1100)
D6  USERCOMPTEXT3: TOSHIBA  [CHIP-2012]  (hidden comment: BAS316)
D7  USERCOMPTEXT3: TOSHIBA  [CHIP-2012]  (hidden comment: BAS316)
D8  DZ2J110M0L  [SC90A]
D9  USERCOMPTEXT3: TOSHIBA  [CHIP-2012]  (hidden comment: BAS316)
D10  USERCOMPTEXT3: TOSHIBA  [CHIP-2012]  (hidden comment: BAS316)
D11  DZ2J110M0L  [SC90A]
IC6  NJM2831F-05  [SOT23-5]
L2  VAL2: 65A  VAL1: 1uH  VAL3: IHTH1125KZEB1R0M5A  [RADIAL-2]  (hidden comment: 1uH-M)
L3  1uH-M  [RADIAL-2]  (value not drawn)
Q3  USERCOMPTEXT3: TOSHIBA  VAL3: 2SC5886A  (hidden comment: TRNL)
Q4  USERCOMPTEXT3: TOSHIBA  [P-MOLD]  (hidden comment: 2SC5886A)
Q5  USERCOMPTEXT3: TOSHIBA  [SO-8]  (hidden comment: TPHR6503PL)
Q6  USERCOMPTEXT3: TOSHIBA  [SO-8]  (hidden comment: TPHR6503PL)
Q7  USERCOMPTEXT3: TOSHIBA  [SO-8]  (hidden comment: TPHR6503PL)
Q8  USERCOMPTEXT3: TOSHIBA  [SO-8]  (hidden comment: TPHR6503PL)
R11  VAL1: 2.2k(J)  COMPCOMMENT: 2012  [CHIP-2012]  (hidden comment: 2k2-J_2012)
R43  COMPCOMMENT: 2012  VAL1: 2.2k(J)  [CHIP-2012]  (hidden comment: 2k2-J_2012)
R44  VAL1: 10(J)  COMPCOMMENT: 2012  [CHIP-2012]  (hidden comment: 10-J_2012)
R45  VAL1: 10(J)  COMPCOMMENT: 2012  [CHIP-2012]  (hidden comment: 10-J_2012)
R46  VAL1: 10(J)  COMPCOMMENT: 2012  [CHIP-2012]  (hidden comment: 10-J_2012)
R47  VAL1: 10(J)  COMPCOMMENT: 2012  [CHIP-2012]  (hidden comment: 10-J_2012)
R48  VAL1: 100(J)  NOTMOUNT: NOT MOUNT  VAL2: 2W  [Axial-2]  (hidden comment: NM_2W)
T1  MAIN-TRANS  VAL3: PC40_EER-28
U?#3  DATE: 2018-11-02  FUNCTION: Synchronous Rectifier & Output  DRAWINGNUMBER: RD040-SCHEMATIC-01  SHEETNUMBER: 3/4  REVISION: 00  TITLE: 1.2V/100A Output DC-DC Converter / Compliant with 48V Bus Voltage  (hidden comment: WAKU_DEF100_2018)

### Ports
0_10V, 0_GND, I_10V, O_5V, O_GND, PN

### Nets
N04057: T1.1 ; off-sheet N04057
N17106: Q5.G R44.1
N17193: Q6.G R45.1
N17255: Q7.G R46.1
N17317: Q8.G R47.1
N17411: C51.1 Q5.D Q6.D T1.S1 T1.S2
N17449: Q7.D Q8.D R48.1 T1.P1 T1.P2
N17555: R44.2 R45.2 ; off-sheet N17555
N17605: R46.2 R47.2 ; off-sheet N17605
N20539: L2.1 L3.1 T1.Q1 T1.Q2 T1.Q3 T1.Q4
N24537: D6.A D7.C T1.3
N25173: C11.2 C12.1 T1.4
N25453: C11.1 D6.C Q3.2 R11.2
N25757: D8.C Q3.1 R11.1
N27553: T1.2 ; off-sheet N27553
N27715: C51.2 R48.2
N28004: C41.1 C47.1 D9.C Q4.2 R43.2
N28016: D11.C Q4.1 R43.1
N115099: D9.A D10.C T1.6
N115166: C47.2 C48.1 T1.7
OUT+: C52.1 C53.1 C54.1 C55.1 C56.1 C57.1 C58.1 CN2.1 L2.2 L3.2 ; off-sheet OUT+
SIG170: C12.2 C13.2 C14.1 D7.A D8.A ; port PN
NetC13_1: C13.1 Q3.3 ; port I_10V
NetC14_2: C14.2 C41.2 C42.2 C48.2 C52.2 C53.2 C54.2 C55.2 C56.2 C57.2 C58.2 CN3.1 D10.A D11.A Q5.S Q6.S Q7.S Q8.S ; port O_GND
NetC42_1: C42.1 IC6.1 IC6.5 Q4.3 ; port 0_10V
NetC44_1: C44.1 IC6.4 ; port O_5V
NetC44_2: C44.2 IC6.2 ; port 0_GND

Not connected (* = marked no-connect by the designer): IC6 3; T1 5 8 9 10

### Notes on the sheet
- Option
- (near T1) 8T
- (near T1) 1T
- x2
- x4
- (near T1) 3T

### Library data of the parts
C11 = C: OriginalSymbolOrigin: (2540,7620); VAL3: GCM21BR71H105K; COMPONENTNAME: C_C; MAKER: Murata; INSTANCENAME: I25290; SAVECOUNT: 1; UPDATETIME: 16:59:57; UPDATEUSER: w20070dm; PIN NAMES VISIBLE: False; PIN NAMES ROTATE: True
C12 = C: OriginalSymbolOrigin: (2540,7620); VAL3: GCM21BR71H105K; COMPONENTNAME: C_C; MAKER: Murata; INSTANCENAME: I25350; SAVECOUNT: 1; UPDATETIME: 16:59:57; UPDATEUSER: w20070dm; PIN NAMES VISIBLE: False; PIN NAMES ROTATE: True
C13 = C: OriginalSymbolOrigin: (2540,7620); VAL3: GCM21BR71H105K; COMPONENTNAME: C_C; MAKER: Murata; INSTANCENAME: I29535; SAVECOUNT: 1; UPDATETIME: 16:59:57; UPDATEUSER: w20070dm; PIN NAMES VISIBLE: False; PIN NAMES ROTATE: True
C14 = C: OriginalSymbolOrigin: (2540,7620); VAL3: ECWH20222JV; COMPONENTNAME: C_C; MAKER: Panasonic; INSTANCENAME: I20635125; SAVECOUNT: 1; UPDATETIME: 16:59:57; UPDATEUSER: w20070dm; PIN NAMES VISIBLE: False; PIN NAMES ROTATE: True
C41 = C: OriginalSymbolOrigin: (2540,7620); VAL3: GRM32ER71E226K; COMPONENTNAME: C_C; MAKER: Murata; INSTANCENAME: I28285; SAVECOUNT: 1; UPDATETIME: 16:59:57; UPDATEUSER: w20070dm; PIN NAMES VISIBLE: False; PIN NAMES ROTATE: True
C42 = C: OriginalSymbolOrigin: (2540,7620); VAL3: GCM21BR71H105K; COMPONENTNAME: C_C; MAKER: Murata; INSTANCENAME: I29753; SAVECOUNT: 1; UPDATETIME: 16:59:57; UPDATEUSER: w20070dm; PIN NAMES VISIBLE: False; PIN NAMES ROTATE: True
C44 = C: OriginalSymbolOrigin: (2540,7620); VAL3: GCM32ER71E106K; COMPONENTNAME: C_C; MAKER: Murata; TYPE: GCM32ER71H106K; INSTANCENAME: I96322; SAVECOUNT: 1; UPDATETIME: 16:59:57; UPDATEUSER: w20070dm; PIN NAMES VISIBLE: False; PIN NAMES ROTATE: True
C47 = C: OriginalSymbolOrigin: (2540,7620); VAL3: GCM21BR71H105K; COMPONENTNAME: C_C; MAKER: Murata; INSTANCENAME: I115041; SAVECOUNT: 1; UPDATETIME: 16:59:57; UPDATEUSER: w20070dm; PIN NAMES VISIBLE: False; PIN NAMES ROTATE: True
C48 = C: OriginalSymbolOrigin: (2540,7620); VAL3: GCM21BR71H105K; COMPONENTNAME: C_C; MAKER: Murata; INSTANCENAME: I115081; SAVECOUNT: 1; UPDATETIME: 16:59:57; UPDATEUSER: w20070dm; PIN NAMES VISIBLE: False; PIN NAMES ROTATE: True
C51 = C: OriginalSymbolOrigin: (2540,7620); VAL3: ECQE2225KB; COMPONENTNAME: C_C; MAKER: Panasonic; INSTANCENAME: I27743; SAVECOUNT: 1; UPDATETIME: 16:59:57; UPDATEUSER: w20070dm; PIN NAMES VISIBLE: False; PIN NAMES ROTATE: True
C52 = C: OriginalSymbolOrigin: (2540,7620); VAL3: AMK432BJ477MM; COMPONENTNAME: C_C; MAKER: Taiyo-Yuden; INSTANCENAME: I19086; SAVECOUNT: 1; UPDATETIME: 16:59:57; UPDATEUSER: w20070dm; PIN NAMES VISIBLE: False; PIN NAMES ROTATE: True
C53 = C: OriginalSymbolOrigin: (2540,7620); VAL3: AMK432BJ477MM; VAL2: 4V; VAL1: 470uF(M); COMPCOMMENT: 4532; COMPONENTNAME: C_C; MAKER: Taiyo-Yuden; INSTANCENAME: I19062; SAVECOUNT: 1; UPDATETIME: 16:59:57; UPDATEUSER: w20070dm; PIN NAMES VISIBLE: False; PIN NAMES ROTATE: True
C54 = C: OriginalSymbolOrigin: (2540,7620); VAL3: AMK432BJ477MM; VAL2: 4V; VAL1: 470uF(M); COMPCOMMENT: 4532; COMPONENTNAME: C_C; MAKER: Taiyo-Yuden; INSTANCENAME: I19038; SAVECOUNT: 1; UPDATETIME: 16:59:57; UPDATEUSER: w20070dm; PIN NAMES VISIBLE: False; PIN NAMES ROTATE: True
C55 = C: OriginalSymbolOrigin: (2540,7620); VAL3: AMK432BJ477MM; VAL2: 4V; VAL1: 470uF(M); COMPCOMMENT: 4532; COMPONENTNAME: C_C; MAKER: Taiyo-Yuden; INSTANCENAME: I18954; SAVECOUNT: 1; UPDATETIME: 16:59:57; UPDATEUSER: w20070dm; PIN NAMES VISIBLE: False; PIN NAMES ROTATE: True
C56 = C: OriginalSymbolOrigin: (2540,7620); VAL3: GRM32ER71E226K; COMPONENTNAME: C_C; MAKER: Murata; INSTANCENAME: I18705; SAVECOUNT: 1; UPDATETIME: 16:59:57; UPDATEUSER: w20070dm; PIN NAMES VISIBLE: False; PIN NAMES ROTATE: True
C57 = C: OriginalSymbolOrigin: (2540,7620); VAL2: 25V; VAL1: 22uF(K); VAL3: GRM32ER71E226K; COMPCOMMENT: 3225; COMPONENTNAME: C_C; MAKER: Murata; INSTANCENAME: I19014; SAVECOUNT: 1; UPDATETIME: 16:59:57; UPDATEUSER: w20070dm; PIN NAMES VISIBLE: False; PIN NAMES ROTATE: True
C58 = C: OriginalSymbolOrigin: (2540,7620); VAL3: GCM21BR71H105K; COMPONENTNAME: C_C; MAKER: Murata; INSTANCENAME: I18657; SAVECOUNT: 1; UPDATETIME: 16:59:57; UPDATEUSER: w20070dm; PIN NAMES VISIBLE: False; PIN NAMES ROTATE: True
CN2 = CN1: OriginalSymbolOrigin: (2540,12700); FUNCTION: TestPin(short)_TestPin(short).Normal_package; MAKER: Osada; INSTANCENAME: I22103497; SAVECOUNT: 1; UPDATETIME: 16:59:57; UPDATEUSER: w20070dm; PIN NAMES VISIBLE: False; PIN NAMES ROTATE: True
CN3 = CN1: OriginalSymbolOrigin: (2540,12700); FUNCTION: TestPin(short)_TestPin(short).Normal_package; MAKER: Osada; INSTANCENAME: I23904; SAVECOUNT: 1; UPDATETIME: 16:59:57; UPDATEUSER: w20070dm; PIN NAMES VISIBLE: False; PIN NAMES ROTATE: True
D6 = D: PARTNAME: DIODE; SAVEAREA0: -225,-91,12804,7836; SAVECOUNT: 3; TIME: 14:49:55; UPDATEUSER: 19870035; UPDATETIME: 14:20:16; OriginalSymbolOrigin: (5080,5080); COMPONENTNAME: DIODE_DIODE; INSTANCENAME: I24616; NUMBER DEVICES IN PACKAGE: 1; PIN NAMES VISIBLE: False; PIN NAMES ROTATE: True
D7 = D: PARTNAME: DIODE; SAVEAREA0: -225,-91,12804,7836; SAVECOUNT: 3; TIME: 14:49:55; UPDATEUSER: 19870035; UPDATETIME: 14:20:16; OriginalSymbolOrigin: (5080,5080); COMPONENTNAME: DIODE_DIODE; INSTANCENAME: I24652; NUMBER DEVICES IN PACKAGE: 1; PIN NAMES VISIBLE: False; PIN NAMES ROTATE: True
D8 = ZD: PARTNAME: DIODE ZENER; SAVEAREA0: -4630,-153,17114,13055; TIME: 14:49:55; UPDATEUSER: fukuda-y; UPDATETIME: 08:18:42; SAVECOUNT: 6; OriginalSymbolOrigin: (5080,5080); COMPONENTNAME: DIODE ZENER_DIODE ZENER; MAKER: Panasonic; INSTANCENAME: I20621212; NUMBER DEVICES IN PACKAGE: 1; PIN NAMES VISIBLE: False; PIN NAMES ROTATE: True
D9 = D: PARTNAME: DIODE; SAVEAREA0: -225,-91,12804,7836; SAVECOUNT: 3; TIME: 14:49:55; UPDATEUSER: 19870035; UPDATETIME: 14:20:16; OriginalSymbolOrigin: (5080,5080); COMPONENTNAME: DIODE_DIODE; INSTANCENAME: I30564; NUMBER DEVICES IN PACKAGE: 1; PIN NAMES VISIBLE: False; PIN NAMES ROTATE: True
D10 = D: PARTNAME: DIODE; SAVEAREA0: -225,-91,12804,7836; SAVECOUNT: 3; TIME: 14:49:55; UPDATEUSER: 19870035; UPDATETIME: 14:20:16; OriginalSymbolOrigin: (5080,5080); COMPONENTNAME: DIODE_DIODE; INSTANCENAME: I30540; NUMBER DEVICES IN PACKAGE: 1; PIN NAMES VISIBLE: False; PIN NAMES ROTATE: True
D11 = ZD: PARTNAME: DIODE ZENER; SAVEAREA0: -4630,-153,17114,13055; TIME: 14:49:55; UPDATEUSER: fukuda-y; UPDATETIME: 08:18:42; SAVECOUNT: 6; OriginalSymbolOrigin: (5080,5080); COMPONENTNAME: DIODE ZENER_DIODE ZENER; MAKER: Panasonic; INSTANCENAME: I22176; NUMBER DEVICES IN PACKAGE: 1; PIN NAMES VISIBLE: False; PIN NAMES ROTATE: True
IC6 = L2831F: SAVECOUNT: 29; SAVEAREA0: -12415,-12415,55780,32568; TIME: 17:38:05; UPDATEUSER: cae; UPDATETIME: 11:39:08; OriginalSymbolOrigin: (7620,25400); FUNCTION: NJM2831F_NJM2831F.Normal_package; MAKER: NJR; INSTANCENAME: I111366; NUMBER DEVICES IN PACKAGE: 1; PIN NAMES VISIBLE: True
L2 = L: PARTNAME: INDUCTOR; OriginalSymbolOrigin: (2540,5080); COMPONENTNAME: INDUCTOR_INDUCTOR; MAKER: Vishay; INSTANCENAME: I18633; SAVECOUNT: 1; UPDATETIME: 16:59:57; UPDATEUSER: w20070dm; PIN NAMES VISIBLE: False; ORDER: 0; PIN NAMES ROTATE: True
L3 = L: PARTNAME: INDUCTOR; OriginalSymbolOrigin: (2540,5080); VAL3: IHTH1125KZEB1R0M5A; VAL2: 65A; VAL1: 1uH; COMPONENTNAME: INDUCTOR_INDUCTOR; MAKER: Vishay; INSTANCENAME: I21382; SAVECOUNT: 1; UPDATETIME: 16:59:57; UPDATEUSER: w20070dm; PIN NAMES VISIBLE: False; ORDER: 0; PIN NAMES ROTATE: True
Q3 = TRNL: PARTNAME: NPNBCE; TIME: 09:39:04; UPDATEUSER: cae; UPDATETIME: 11:17:06; SAVECOUNT: 9; SAVEAREA0: -6161,-458,18680,15927; OriginalSymbolOrigin: (2540,17780)
Q4 = TRNL: PARTNAME: NPN BCE; TIME: 09:39:04; UPDATEUSER: cae; UPDATETIME: 11:17:06; SAVECOUNT: 9; SAVEAREA0: -6161,-458,18680,15927; OriginalSymbolOrigin: (2540,17780); FUNCTION: NPN BCE_NPN BCE.Normal_package; INSTANCENAME: I28100; NUMBER DEVICES IN PACKAGE: 1; PIN NAMES VISIBLE: False; ORDER: 0; PIN NAMES ROTATE: True
Q5 = MFNF: PARTNAME: MOSFET_N(D); SAVECOUNT: 11; SAVEAREA0: -7027,-292,21786,15988; OriginalSymbolOrigin: (5080,12700); FUNCTION: MOSFET_N(D)_MOSFET_N(D).Normal_package; INSTANCENAME: I18597; UPDATETIME: 16:59:57; UPDATEUSER: w20070dm; NUMBER DEVICES IN PACKAGE: 1; PIN NAMES VISIBLE: False; PIN NAMES ROTATE: True
Q6 = MFNF: PARTNAME: MOSFET_N(D); SAVECOUNT: 11; SAVEAREA0: -7027,-292,21786,15988; OriginalSymbolOrigin: (5080,12700); FUNCTION: MOSFET_N(D)_MOSFET_N(D).Normal_package; INSTANCENAME: I18557; UPDATETIME: 16:59:57; UPDATEUSER: w20070dm; NUMBER DEVICES IN PACKAGE: 1; PIN NAMES VISIBLE: False; PIN NAMES ROTATE: True
Q7 = MFNF: PARTNAME: MOSFET_N(D); SAVECOUNT: 11; SAVEAREA0: -7027,-292,21786,15988; OriginalSymbolOrigin: (5080,12700); FUNCTION: MOSFET_N(D)_MOSFET_N(D).Normal_package; INSTANCENAME: I18517; UPDATETIME: 16:59:57; UPDATEUSER: w20070dm; NUMBER DEVICES IN PACKAGE: 1; PIN NAMES VISIBLE: False; PIN NAMES ROTATE: True
Q8 = MFNF: PARTNAME: MOSFET_N(D); SAVECOUNT: 11; SAVEAREA0: -7027,-292,21786,15988; OriginalSymbolOrigin: (5080,12700); FUNCTION: MOSFET_N(D)_MOSFET_N(D).Normal_package; INSTANCENAME: I17285; UPDATETIME: 16:59:57; UPDATEUSER: w20070dm; NUMBER DEVICES IN PACKAGE: 1; PIN NAMES VISIBLE: False; PIN NAMES ROTATE: True
R11 = R: OriginalSymbolOrigin: (5080,5080); VAL2: 0.4W; VAL3: ESR10EZPJ222; COMPONENTNAME: R_R; MAKER: ROHM; INSTANCENAME: I25781; SAVECOUNT: 1; UPDATETIME: 16:59:57; UPDATEUSER: w20070dm; PIN NAMES VISIBLE: False; PIN NAMES ROTATE: True
R43 = R: OriginalSymbolOrigin: (5080,5080); VAL2: 0.4W; VAL3: ESR10EZPJ222; COMPONENTNAME: R_R; MAKER: ROHM; INSTANCENAME: I28040; SAVECOUNT: 1; UPDATETIME: 16:59:57; UPDATEUSER: w20070dm; PIN NAMES VISIBLE: False; PIN NAMES ROTATE: True
R44 = R: OriginalSymbolOrigin: (5080,5080); VAL2: 0.4W; VAL3: ESR10EZPJ100; COMPONENTNAME: R_R; MAKER: ROHM; INSTANCENAME: I17028; SAVECOUNT: 1; UPDATETIME: 16:59:57; UPDATEUSER: w20070dm; PIN NAMES VISIBLE: False; PIN NAMES ROTATE: True
R45 = R: OriginalSymbolOrigin: (5080,5080); VAL2: 0.4W; VAL3: ESR10EZPJ100; COMPONENTNAME: R_R; MAKER: ROHM; INSTANCENAME: I17185; SAVECOUNT: 1; UPDATETIME: 16:59:57; UPDATEUSER: w20070dm; PIN NAMES VISIBLE: False; PIN NAMES ROTATE: True
R46 = R: OriginalSymbolOrigin: (5080,5080); VAL2: 0.4W; VAL3: ESR10EZPJ100; COMPONENTNAME: R_R; MAKER: ROHM; INSTANCENAME: I17247; SAVECOUNT: 1; UPDATETIME: 16:59:57; UPDATEUSER: w20070dm; PIN NAMES VISIBLE: False; PIN NAMES ROTATE: True
R47 = R: OriginalSymbolOrigin: (5080,5080); VAL2: 0.4W; VAL3: ESR10EZPJ100; COMPONENTNAME: R_R; MAKER: ROHM; INSTANCENAME: I17309; SAVECOUNT: 1; UPDATETIME: 16:59:57; UPDATEUSER: w20070dm; PIN NAMES VISIBLE: False; PIN NAMES ROTATE: True
R48 = R: OriginalSymbolOrigin: (5080,5080); VAL3: MOS2CT52A101J; COMPONENTNAME: R_R; MAKER: ROHM; INSTANCENAME: I27703; SAVECOUNT: 1; UPDATETIME: 16:59:57; UPDATEUSER: w20070dm; PIN NAMES VISIBLE: False; PIN NAMES ROTATE: True
T1 = PC40-EER28: PARTNAME: AF-TRANS(5A); TIME: 10:32:21; UPDATEUSER: cae; UPDATETIME: 16:55:25; SAVECOUNT: 8; SAVEAREA0: -47471,-620,69376,60068; OriginalSymbolOrigin: (5080,55880); FUNCTION: AF-TRANS(5A)_AF-TRANS(5A).Normal_package; MAKER: TDK; INSTANCENAME: I20627; NUMBER DEVICES IN PACKAGE: 1; PIN NAMES VISIBLE: False; ORDER: 0; PIN NUMBERS VISIBLE: True
U?#3 = WAKU_DEF100_2018: as U?#2 on sheet 2

## Sheet 4.SchDoc
size 420 x 297 mm
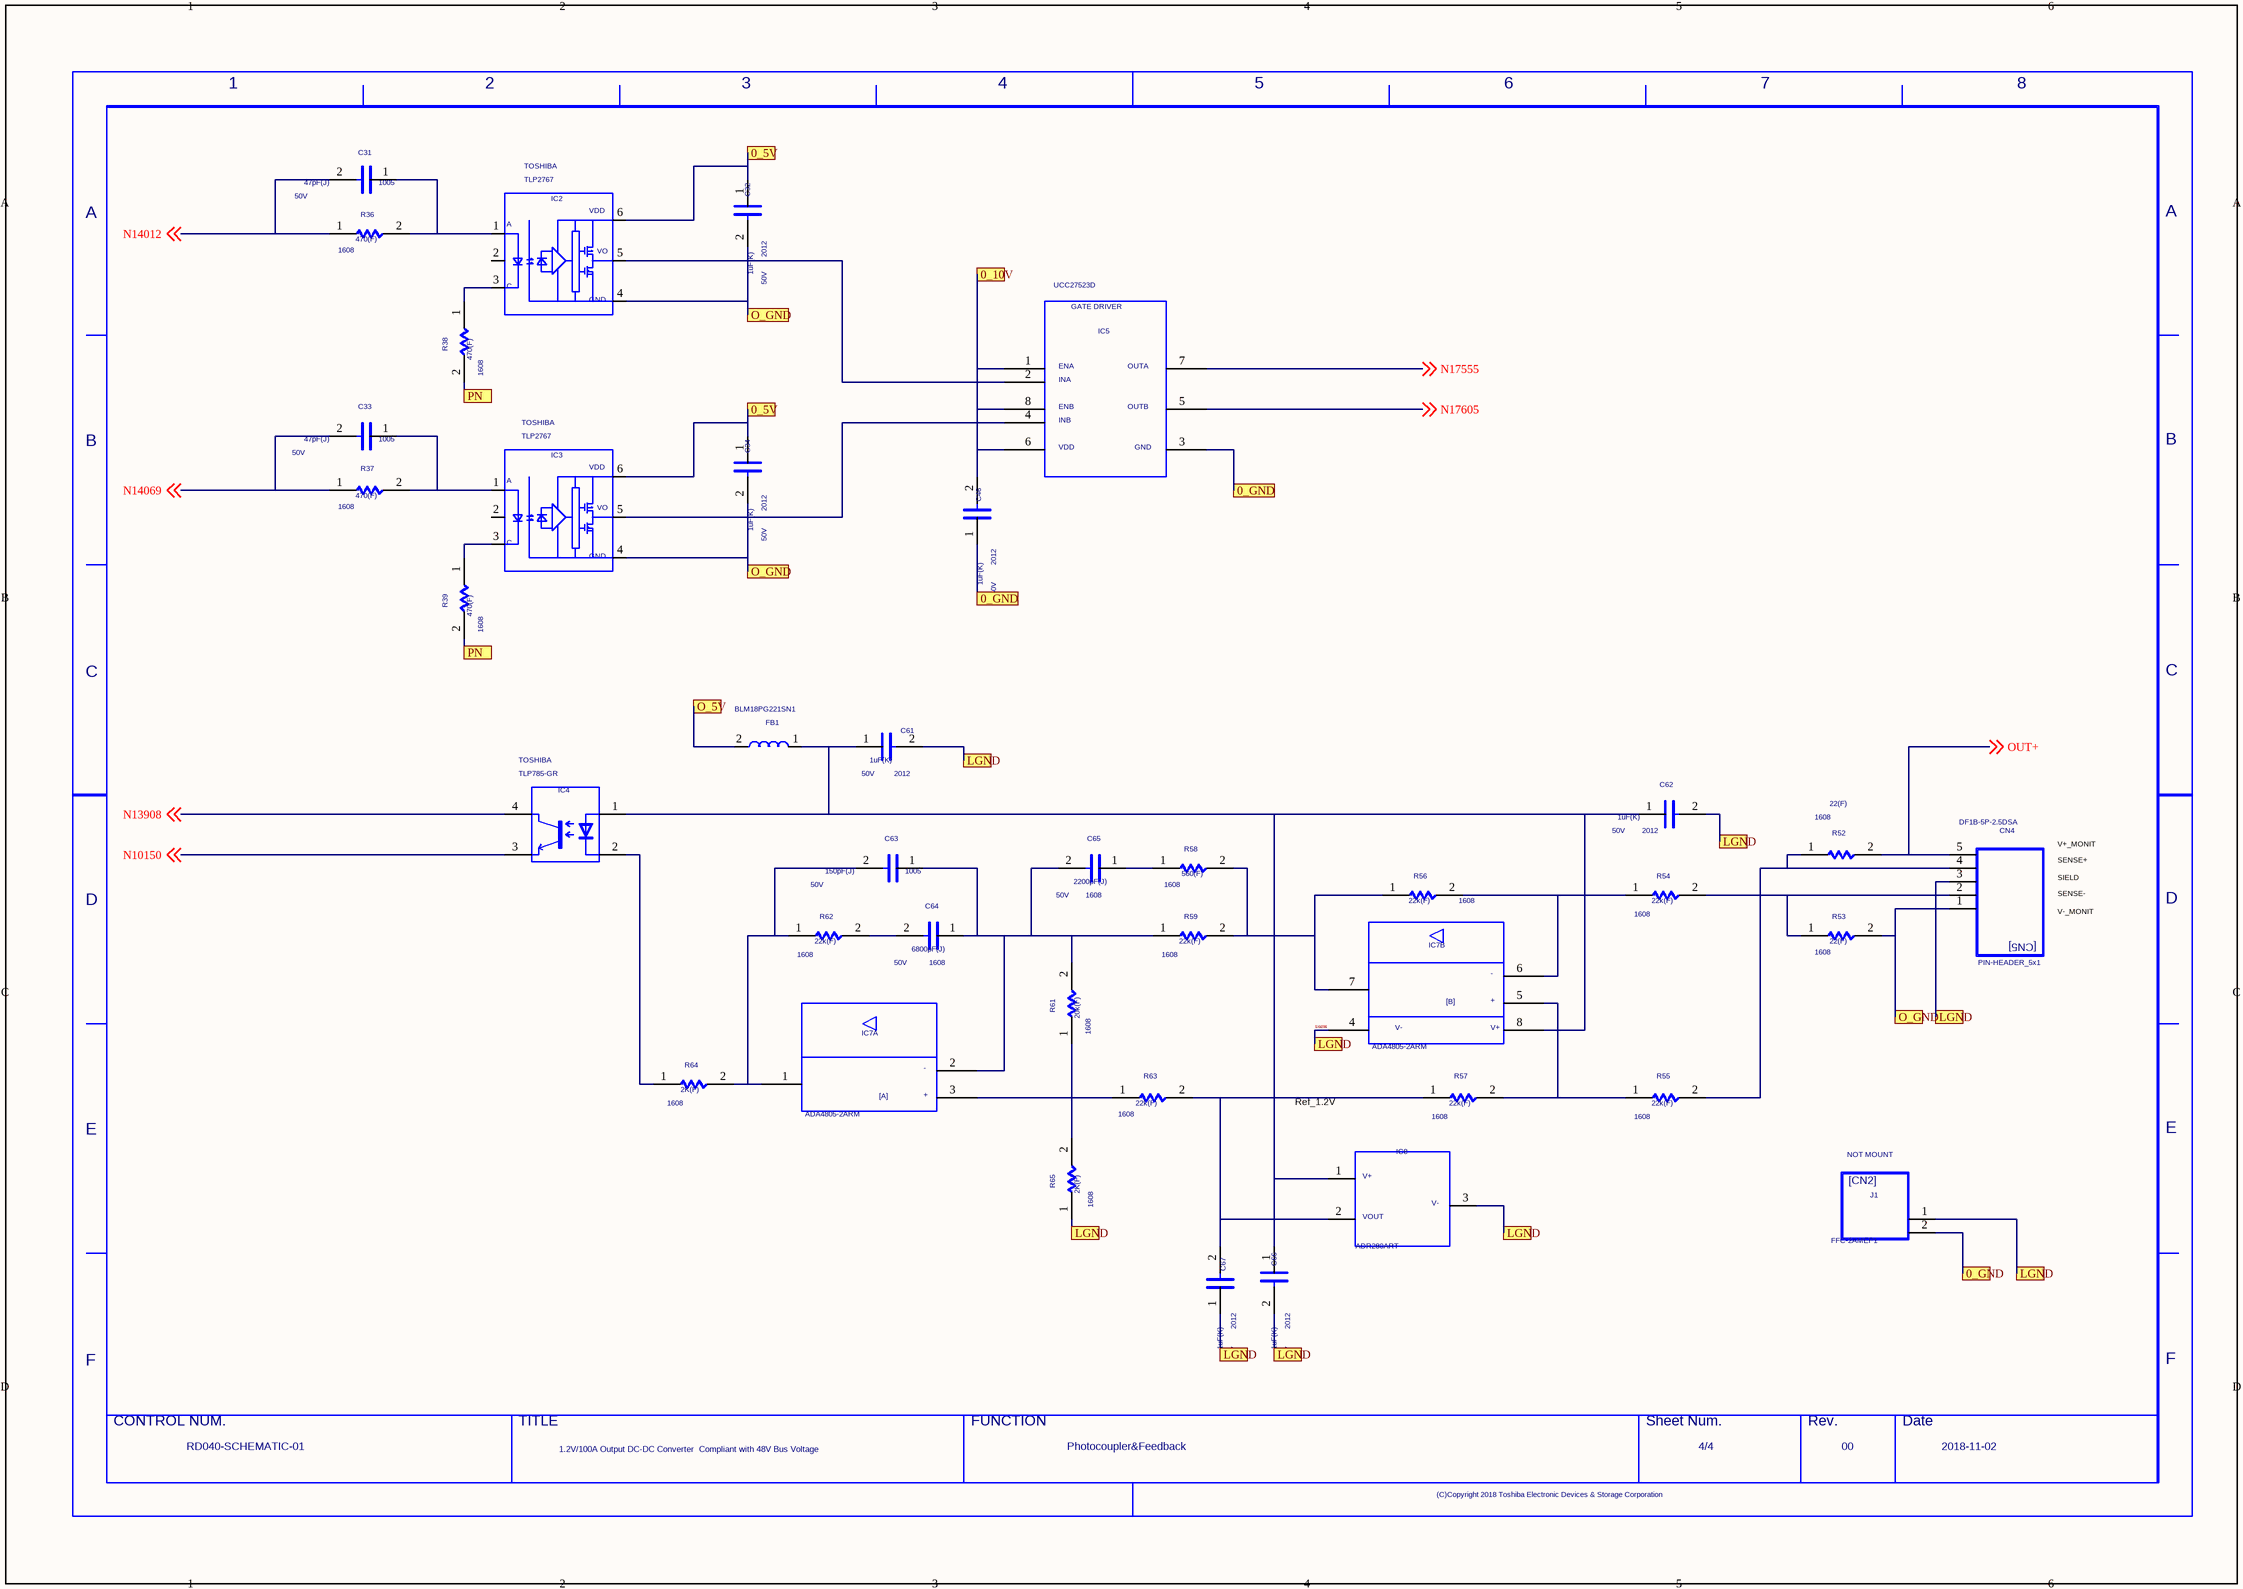
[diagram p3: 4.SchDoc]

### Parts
(Parts that share a designator on the sheet are numbered #1, #2 ... from top to bottom, then left to right.)
C31  VAL2: 50V  COMPCOMMENT: 1005  VAL1: 47pF(J)  [CHIP-1005]  (hidden comment: 47pF-J_1005)
C32  VAL2: 50V  VAL1: 1uF(K)  COMPCOMMENT: 2012  [CHIP-2012]  (hidden comment: 1uF-K_2012)
C33  VAL2: 50V  VAL1: 47pF(J)  COMPCOMMENT: 1005  [CHIP-1005]  (hidden comment: 47pF-J_1005)
C34  VAL2: 50V  COMPCOMMENT: 2012  VAL1: 1uF(K)  [CHIP-2012]  (hidden comment: 1uF-K_2012)
C46  VAL2: 50V  VAL1: 1uF(K)  COMPCOMMENT: 2012  [CHIP-2012]  (hidden comment: 1uF-K_2012)
C61  VAL2: 50V  VAL1: 1uF(K)  COMPCOMMENT: 2012  [CHIP-2012]  (hidden comment: 1uF-K_2012)
C62  COMPCOMMENT: 2012  VAL2: 50V  VAL1: 1uF(K)  [CHIP-2012]  (hidden comment: 1uF-K_2012)
C63  COMPCOMMENT: 1005  VAL2: 50V  VAL1: 150pF(J)  [CHIP-1005]  (hidden comment: 150pF-J_1005)
C64  VAL2: 50V  VAL1: 6800pF(J)  COMPCOMMENT: 1608  [CHIP-1608]  (hidden comment: 6800pF-J_1608)
C65  VAL2: 50V  VAL1: 2200pF(J)  COMPCOMMENT: 1608  [CHIP-1608]  (hidden comment: 2200pF-J_1608)
C66  VAL2: 50V  VAL1: 1uF(K)  COMPCOMMENT: 2012  [CHIP-2012]  (hidden comment: 1uF-K_2012)
C67  VAL2: 50V  VAL1: 1uF(K)  COMPCOMMENT: 2012  [CHIP-2012]  (hidden comment: 1uF-K_2012)
CN4  PARTNAME: PIN-HEADER_5x1  [SIP-5]  (hidden comment: DF1B-5P-2.5DSA)
FB1  VAL3: BLM18PG221SN1  [CHIP-1608]  (hidden comment: BLM18PG221)
IC2  USERCOMPTEXT3: TOSHIBA  [TSSOP-6]  (hidden comment: TLP2767)
IC3  USERCOMPTEXT3: TOSHIBA  [TSSOP-6]  (hidden comment: TLP2767)
IC4  USERCOMPTEXT3: TOSHIBA  [DIP-4]  (hidden comment: TLP785-GR)
IC5  UCC27523D  [SO-8]
IC7  VAL3: ADA4805-2ARM  (hidden comment: L4805_1)  (parts A,B of 2)
IC8  VAL3: ADR280ART  (hidden comment: L280)
J1  NOTMOUNT: NOT MOUNT  VAL3: FFC-2AMEP1  [SIP-2]  (hidden comment: N.M_JUMPER)
R36  COMPCOMMENT: 1608  VAL1: 470(F)  [CHIP-1608]  (hidden comment: 470-F_1608)
R37  VAL1: 470(F)  COMPCOMMENT: 1608  [CHIP-1608]  (hidden comment: 470-F_1608)
R38  VAL1: 470(F)  COMPCOMMENT: 1608  [CHIP-1608]  (hidden comment: 470-F_1608)
R39  VAL1: 470(F)  COMPCOMMENT: 1608  [CHIP-1608]  (hidden comment: 470-F_1608)
R52  VAL1: 22(F)  COMPCOMMENT: 1608  [CHIP-1608]  (hidden comment: 22-F_1608)
R53  VAL1: 22(F)  COMPCOMMENT: 1608  [CHIP-1608]  (hidden comment: 22-F_1608)
R54  VAL1: 22k(F)  COMPCOMMENT: 1608  [CHIP-1608]  (hidden comment: 22k-F_1608)
R55  VAL1: 22k(F)  COMPCOMMENT: 1608  [CHIP-1608]  (hidden comment: 22k-F_1608)
R56  VAL1: 22k(F)  COMPCOMMENT: 1608  [CHIP-1608]  (hidden comment: 22k-F_1608)
R57  VAL1: 22k(F)  COMPCOMMENT: 1608  [CHIP-1608]  (hidden comment: 22k-F_1608)
R58  COMPCOMMENT: 1608  VAL1: 560(F)  [CHIP-1608]  (hidden comment: 560-F_1608)
R59  VAL1: 22k(F)  COMPCOMMENT: 1608  [CHIP-1608]  (hidden comment: 22k-F_1608)
R61  VAL1: 20k(F)  COMPCOMMENT: 1608  [CHIP-1608]  (hidden comment: 20k-F_1608)
R62  VAL1: 22k(F)  COMPCOMMENT: 1608  [CHIP-1608]  (hidden comment: 22k-F_1608)
R63  VAL1: 22k(F)  COMPCOMMENT: 1608  [CHIP-1608]  (hidden comment: 22k-F_1608)
R64  COMPCOMMENT: 1608  VAL1: 2K(F)  [CHIP-1608]  (hidden comment: 2k0-F_1608)
R65  COMPCOMMENT: 1608  VAL1: 2K(F)  [CHIP-1608]  (hidden comment: 2k0-F_1608)
U?#4  DATE: 2018-11-02  FUNCTION: Photocoupler&Feedback  DRAWINGNUMBER: RD040-SCHEMATIC-01  TITLE: 1.2V/100A Output DC-DC Converter / Compliant with 48V Bus Voltage  SHEETNUMBER: 4/4  REVISION: 00  (hidden comment: WAKU_DEF100_2018)

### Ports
0_5V, 0_10V, 0_GND, LGND, O_5V, O_GND, PN

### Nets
N10150: IC4.3 ; off-sheet N10150
N13908: IC4.4 ; off-sheet N13908
N14012: C31.2 R36.1 ; off-sheet N14012
N14069: C33.2 R37.1 ; off-sheet N14069
N17555: IC5.7 ; off-sheet N17555
N17605: IC5.5 ; off-sheet N17605
N32717: C61.1 C62.1 C66.1 FB1.1 IC4.1 IC7.8 IC8.1
N32808: IC4.2 R64.1
N32839: C63.2 IC7.1 R62.1 R64.2
N33727: IC7.7 R56.1 R58.2 R59.2
N33769: IC7.6 R54.1 R56.2
N33837: IC7.5 R55.1 R57.2
N33896: C67.2 IC8.2 R57.1 R63.2
N34516: C63.1 C64.1 C65.2 IC7.2 R59.1 R61.2
N35926: C65.1 R58.1
N36200: C64.2 R62.2
N37152: IC7.3 R63.1
N53493: CN4.2 R53.1 R54.2
N53543: CN4.4 R52.1 R55.2
N56552: R61.1 R65.2
N80775: IC2.3 R38.1
N80936: C31.1 IC2.1 R36.2
N81048: C33.1 IC3.1 R37.2
N87643: IC2.5 IC5.2
N87699: IC3.5 IC5.4
N106339: IC3.3 R39.1
OUT+: CN4.5 R52.2 ; off-sheet OUT+
SIG170: R38.2 R39.2 ; port PN
SIG235: C61.2 C62.2 C66.2 C67.1 CN4.3 IC7.4 IC8.3 J1.1 R65.1 ; port LGND
NetC14_2: C32.2 C34.2 CN4.1 IC2.4 IC3.4 R53.2 ; port O_GND
NetC32_1: C32.1 C34.1 IC2.6 IC3.6 ; port 0_5V
NetC42_1: C46.2 IC5.1 IC5.6 IC5.8 ; port 0_10V
NetC44_1: FB1.2 ; port O_5V
NetC44_2: C46.1 IC5.3 J1.2 ; port 0_GND

Not connected (* = marked no-connect by the designer): IC2 2; IC3 2

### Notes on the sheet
- SENSE+
- V+_MONIT
- SIELD
- V-_MONIT
- SENSE-
- Ref_1.2V

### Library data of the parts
C31 = C: OriginalSymbolOrigin: (2540,7620); VAL3: GRM1552C1H470J; COMPONENTNAME: C_C; MAKER: MURATA; INSTANCENAME: I80858; SAVECOUNT: 1; UPDATETIME: 16:59:57; UPDATEUSER: w20070dm; PIN NAMES VISIBLE: False; PIN NAMES ROTATE: True
C32 = C: OriginalSymbolOrigin: (2540,7620); VAL3: GCM21BR71H105K; COMPONENTNAME: C_C; MAKER: Murata; INSTANCENAME: I91091; SAVECOUNT: 1; UPDATETIME: 16:59:57; UPDATEUSER: w20070dm; PIN NAMES VISIBLE: False; PIN NAMES ROTATE: True
C33 = C: OriginalSymbolOrigin: (2540,7620); VAL3: GRM1552C1H470J; COMPONENTNAME: C_C; MAKER: MURATA; INSTANCENAME: I81096; SAVECOUNT: 1; UPDATETIME: 16:59:57; UPDATEUSER: w20070dm; PIN NAMES VISIBLE: False; PIN NAMES ROTATE: True
C34 = C: OriginalSymbolOrigin: (2540,7620); VAL3: GCM21BR71H105K; COMPONENTNAME: C_C; MAKER: Murata; INSTANCENAME: I91367; SAVECOUNT: 1; UPDATETIME: 16:59:57; UPDATEUSER: w20070dm; PIN NAMES VISIBLE: False; PIN NAMES ROTATE: True
C46 = C: OriginalSymbolOrigin: (2540,7620); VAL3: GCM21BR71H105K; COMPONENTNAME: C_C; MAKER: Murata; INSTANCENAME: I90955; SAVECOUNT: 1; UPDATETIME: 16:59:57; UPDATEUSER: w20070dm; PIN NAMES VISIBLE: False; PIN NAMES ROTATE: True
C61 = C: OriginalSymbolOrigin: (2540,7620); VAL3: GCM21BR71H105K; COMPONENTNAME: C_C; MAKER: Murata; INSTANCENAME: I55413; SAVECOUNT: 1; UPDATETIME: 16:59:57; UPDATEUSER: w20070dm; PIN NAMES VISIBLE: False; PIN NAMES ROTATE: True
C62 = C: OriginalSymbolOrigin: (2540,7620); VAL3: GCM21BR71H105K; COMPONENTNAME: C_C; MAKER: Murata; INSTANCENAME: I36792; SAVECOUNT: 1; UPDATETIME: 16:59:57; UPDATEUSER: w20070dm; PIN NAMES VISIBLE: False; PIN NAMES ROTATE: True
C63 = C: OriginalSymbolOrigin: (2540,7620); VAL3: GRM1552C1H151J; COMPONENTNAME: C_C; MAKER: MURATA; INSTANCENAME: I36377; SAVECOUNT: 1; UPDATETIME: 16:59:57; UPDATEUSER: w20070dm; PIN NAMES VISIBLE: False; PIN NAMES ROTATE: True
C64 = C: OriginalSymbolOrigin: (2540,7620); VAL3: GRM1882C1H682J; COMPONENTNAME: C_C; MAKER: MURATA; INSTANCENAME: I36005; SAVECOUNT: 1; UPDATETIME: 16:59:57; UPDATEUSER: w20070dm; PIN NAMES VISIBLE: False; PIN NAMES ROTATE: True
C65 = C: OriginalSymbolOrigin: (2540,7620); VAL3: GRM1882C1H222J; COMPONENTNAME: C_C; MAKER: MURATA; INSTANCENAME: I34854; SAVECOUNT: 1; UPDATETIME: 16:59:57; UPDATEUSER: w20070dm; PIN NAMES VISIBLE: False; PIN NAMES ROTATE: True
C66 = C: OriginalSymbolOrigin: (2540,7620); VAL3: GCM21BR71H105K; COMPONENTNAME: C_C; MAKER: Murata; INSTANCENAME: I55902; SAVECOUNT: 1; UPDATETIME: 16:59:57; UPDATEUSER: w20070dm; PIN NAMES VISIBLE: False; PIN NAMES ROTATE: True
C67 = C: OriginalSymbolOrigin: (2540,7620); VAL3: GCM21BR71H105K; COMPONENTNAME: C_C; MAKER: Murata; INSTANCENAME: I55952; SAVECOUNT: 1; UPDATETIME: 16:59:57; UPDATEUSER: w20070dm; PIN NAMES VISIBLE: False; PIN NAMES ROTATE: True
CN4 = CN5: OriginalSymbolOrigin: (2540,22860); FUNCTION: PIN-HEADER_5x1_PIN-HEADER_5x1.Normal_package; MAKER: HIROSE; INSTANCENAME: I21634261; SAVECOUNT: 1; UPDATETIME: 16:59:57; UPDATEUSER: w20070dm; PIN NAMES VISIBLE: False; PIN NAMES ROTATE: True
FB1 = L: PARTNAME: INDUCTOR; OriginalSymbolOrigin: (2540,5080); COMPONENTNAME: INDUCTOR_INDUCTOR; MAKER: MURATA; INSTANCENAME: I21939901; SAVECOUNT: 1; UPDATETIME: 16:59:57; UPDATEUSER: w20070dm; PIN NAMES VISIBLE: False; ORDER: 0; PIN NAMES ROTATE: True
IC2 = TLP2767: TIME: 11:37:10; UPDATEUSER: cae; UPDATETIME: 18:11:01; SAVECOUNT: 22; SAVEAREA0: -386,-6396,25843,34300; OriginalSymbolOrigin: (2540,25400); FUNCTION: TLP2767_TLP2767.Normal_package; INSTANCENAME: I79931; NUMBER DEVICES IN PACKAGE: 1; PIN NAMES VISIBLE: False; PIN NAMES ROTATE: True
IC3 = TLP2767: TIME: 11:37:10; UPDATEUSER: cae; UPDATETIME: 18:11:01; SAVECOUNT: 22; SAVEAREA0: -386,-6396,25843,34300; OriginalSymbolOrigin: (2540,25400); FUNCTION: TLP2767_TLP2767.Normal_package; INSTANCENAME: I80693; NUMBER DEVICES IN PACKAGE: 1; PIN NAMES VISIBLE: False; PIN NAMES ROTATE: True
IC4 = TLP785: PARTNAME: TLP291; SAVEAREA0: -2309,-355,24620,17408; TIME: 13:47:14; UPDATEUSER: cae; SAVECOUNT: 1; OriginalSymbolOrigin: (5080,15240); FUNCTION: TLP291_TLP291.Normal_package; INSTANCENAME: I21316553; PIN NAMES VISIBLE: False; PIN NAMES ROTATE: True
IC5 = L27523: SAVEAREA0: -10704,-787,48955,38565; SAVECOUNT: 17; TIME: 12:23:18; UPDATEUSER: cae; UPDATETIME: 08:35:05; OriginalSymbolOrigin: (7620,35560); FUNCTION: UCC27523D_UCC27523D.Normal_package; MAKER: T.I.; INSTANCENAME: I87495; NUMBER DEVICES IN PACKAGE: 1; PIN NAMES VISIBLE: True
IC7 = L4805_1: SAVECOUNT: 184; SAVEAREA0: -7024,-4200,47866,32007; TIME: 22:14:29; UPDATEUSER: cae; UPDATETIME: 16:00:05; FUNCTION: OP-AMP(DUAL)_2; OriginalSymbolOrigin: (7620,25400); CaptureCellPackProp: L4805_1A
IC8 = L280: SAVECOUNT: 18; SAVEAREA0: -9081,-242,36640,23504; TIME: 17:47:02; UPDATEUSER: cae; UPDATETIME: 15:11:54; OriginalSymbolOrigin: (5080,20320)
J1 = CN2: PARTNAME: PIN-HEADER_2x1(A); OriginalSymbolOrigin: (2540,15240); COMPONENTNAME: PIN-HEADER_2x1(A)_PIN-HEADER_2x1(A); MAKER: HONDA; INSTANCENAME: I39896; SAVECOUNT: 1; UPDATETIME: 16:59:57; UPDATEUSER: w20070dm; PIN NAMES VISIBLE: False; PIN NAMES ROTATE: True
R36 = R: OriginalSymbolOrigin: (5080,5080); VAL2: 1/10W; VAL3: RK73H1JTTD4700F; COMPONENTNAME: R_R; MAKER: KOA; INSTANCENAME: I80721; SAVECOUNT: 1; UPDATETIME: 16:59:57; UPDATEUSER: w20070dm; PIN NAMES VISIBLE: False; PIN NAMES ROTATE: True
R37 = R: OriginalSymbolOrigin: (5080,5080); VAL3: RK73H1JTTD4700F; VAL2: 1/10W; COMPONENTNAME: R_R; MAKER: KOA; INSTANCENAME: I105808; SAVECOUNT: 1; UPDATETIME: 16:59:57; UPDATEUSER: w20070dm; PIN NAMES VISIBLE: False; PIN NAMES ROTATE: True
R38 = R: OriginalSymbolOrigin: (5080,5080); VAL2: 1/10W; VAL3: RK73H1JTTD4700F; COMPONENTNAME: R_R; MAKER: KOA; INSTANCENAME: I105857; SAVECOUNT: 1; UPDATETIME: 16:59:57; UPDATEUSER: w20070dm; PIN NAMES VISIBLE: False; PIN NAMES ROTATE: True
R39 = R: OriginalSymbolOrigin: (5080,5080); VAL3: RK73H1JTTD4700F; VAL2: 1/10W; COMPONENTNAME: R_R; MAKER: KOA; INSTANCENAME: I106383; SAVECOUNT: 1; UPDATETIME: 16:59:57; UPDATEUSER: w20070dm; PIN NAMES VISIBLE: False; PIN NAMES ROTATE: True
R52 = R: OriginalSymbolOrigin: (5080,5080); VAL3: RK73H1JTTD22R0F; COMPONENTNAME: R_R; MAKER: KOA; INSTANCENAME: I53738; SAVECOUNT: 1; UPDATETIME: 16:59:57; UPDATEUSER: w20070dm; PIN NAMES VISIBLE: False; PIN NAMES ROTATE: True
R53 = R: OriginalSymbolOrigin: (5080,5080); VAL3: RK73H1JTTD22R0F; COMPONENTNAME: R_R; MAKER: KOA; INSTANCENAME: I53644; SAVECOUNT: 1; UPDATETIME: 16:59:57; UPDATEUSER: w20070dm; PIN NAMES VISIBLE: False; PIN NAMES ROTATE: True
R54 = R: OriginalSymbolOrigin: (5080,5080); VAL3: RK73H1JTTD2202F; COMPONENTNAME: R_R; MAKER: KOA; INSTANCENAME: I33721; SAVECOUNT: 1; UPDATETIME: 16:59:57; UPDATEUSER: w20070dm; PIN NAMES VISIBLE: False; PIN NAMES ROTATE: True
R55 = R: OriginalSymbolOrigin: (5080,5080); VAL3: RK73H1JTTD2202F; COMPONENTNAME: R_R; MAKER: KOA; INSTANCENAME: I33880; SAVECOUNT: 1; UPDATETIME: 16:59:57; UPDATEUSER: w20070dm; PIN NAMES VISIBLE: False; PIN NAMES ROTATE: True
R56 = R: OriginalSymbolOrigin: (5080,5080); VAL3: RK73H1JTTD2202F; COMPONENTNAME: R_R; MAKER: KOA; INSTANCENAME: I33649; SAVECOUNT: 1; UPDATETIME: 16:59:57; UPDATEUSER: w20070dm; PIN NAMES VISIBLE: False; PIN NAMES ROTATE: True
R57 = R: OriginalSymbolOrigin: (5080,5080); VAL3: RK73H1JTTD2202F; COMPONENTNAME: R_R; MAKER: KOA; INSTANCENAME: I33916; SAVECOUNT: 1; UPDATETIME: 16:59:57; UPDATEUSER: w20070dm; PIN NAMES VISIBLE: False; PIN NAMES ROTATE: True
R58 = R: OriginalSymbolOrigin: (5080,5080); VAL3: RK73H1JTTD5600F; COMPONENTNAME: R_R; MAKER: KOA; INSTANCENAME: I34582; SAVECOUNT: 1; UPDATETIME: 16:59:57; UPDATEUSER: w20070dm; PIN NAMES VISIBLE: False; PIN NAMES ROTATE: True
R59 = R: OriginalSymbolOrigin: (5080,5080); VAL3: RK73H1JTTD2202F; COMPONENTNAME: R_R; MAKER: KOA; INSTANCENAME: I34100; SAVECOUNT: 1; UPDATETIME: 16:59:57; UPDATEUSER: w20070dm; PIN NAMES VISIBLE: False; PIN NAMES ROTATE: True
R61 = R: OriginalSymbolOrigin: (5080,5080); VAL3: RK73H1JTTD2002F; COMPONENTNAME: R_R; MAKER: KOA; INSTANCENAME: I34438; SAVECOUNT: 1; UPDATETIME: 16:59:57; UPDATEUSER: w20070dm; PIN NAMES VISIBLE: False; PIN NAMES ROTATE: True
R62 = R: OriginalSymbolOrigin: (5080,5080); VAL3: RK73H1JTTD2202F; COMPONENTNAME: R_R; MAKER: KOA; INSTANCENAME: I36079; SAVECOUNT: 1; UPDATETIME: 16:59:57; UPDATEUSER: w20070dm; PIN NAMES VISIBLE: False; PIN NAMES ROTATE: True
R63 = R: OriginalSymbolOrigin: (5080,5080); VAL3: RK73H1JTTD2202F; COMPONENTNAME: R_R; MAKER: KOA; INSTANCENAME: I37146; SAVECOUNT: 1; UPDATETIME: 16:59:57; UPDATEUSER: w20070dm; PIN NAMES VISIBLE: False; PIN NAMES ROTATE: True
R64 R65 = R: OriginalSymbolOrigin: (5080,5080); VAL3: RK73H1JTTD2001F; COMPONENTNAME: R_R; MAKER: KOA; INSTANCENAME: I32754; SAVECOUNT: 1; UPDATETIME: 16:59:57; UPDATEUSER: w20070dm; PIN NAMES VISIBLE: False; PIN NAMES ROTATE: True
U?#4 = WAKU_DEF100_2018: as U?#2 on sheet 2

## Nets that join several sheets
N03975: 1 (10 pins), 2 (5 pins)
N04057: 1 (9 pins), 3 (T1.1)
N07198: 1 (D1.3 R4.1), 2 (IC1.13)
N07407: 1 (D2.3 R7.1), 2 (IC1.14)
N07475: 1 (Q1.S Q2.D T2.8), 2 (C22.1 IC1.12)
N10150: 2 (IC1.4), 4 (IC4.3)
N13908: 2 (C29.1 IC1.19), 4 (IC4.4)
N14012: 2 (IC1.18), 4 (C31.2 R36.1)
N14069: 2 (IC1.17), 4 (C33.2 R37.1)
N17555: 3 (R44.2 R45.2), 4 (IC5.7)
N17605: 3 (R46.2 R47.2), 4 (IC5.5)
N27553: 1 (C16.1 T2.7), 3 (T1.2)
N78233: 1 (R32.1 T2.1), 2 (D4.3)
N78252: 1 (R32.2 T2.3), 2 (D3.3)
NetC13_1: 2 (C21.2 D5.A IC1.16), 3 (C13.1 Q3.3)
NetC14_2: 3 (18 pins), 4 (6 pins)
NetC42_1: 3 (C42.1 IC6.1 IC6.5 Q4.3), 4 (C46.2 IC5.1 IC5.6 IC5.8)
NetC44_1: 3 (C44.1 IC6.4), 4 (FB1.2)
NetC44_2: 3 (C44.2 IC6.2), 4 (C46.1 IC5.3 J1.2)
OUT+: 3 (10 pins), 4 (CN4.5 R52.2)
SIG170: 1 (9 pins), 2 (19 pins), 3 (5 pins), 4 (R38.2 R39.2)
